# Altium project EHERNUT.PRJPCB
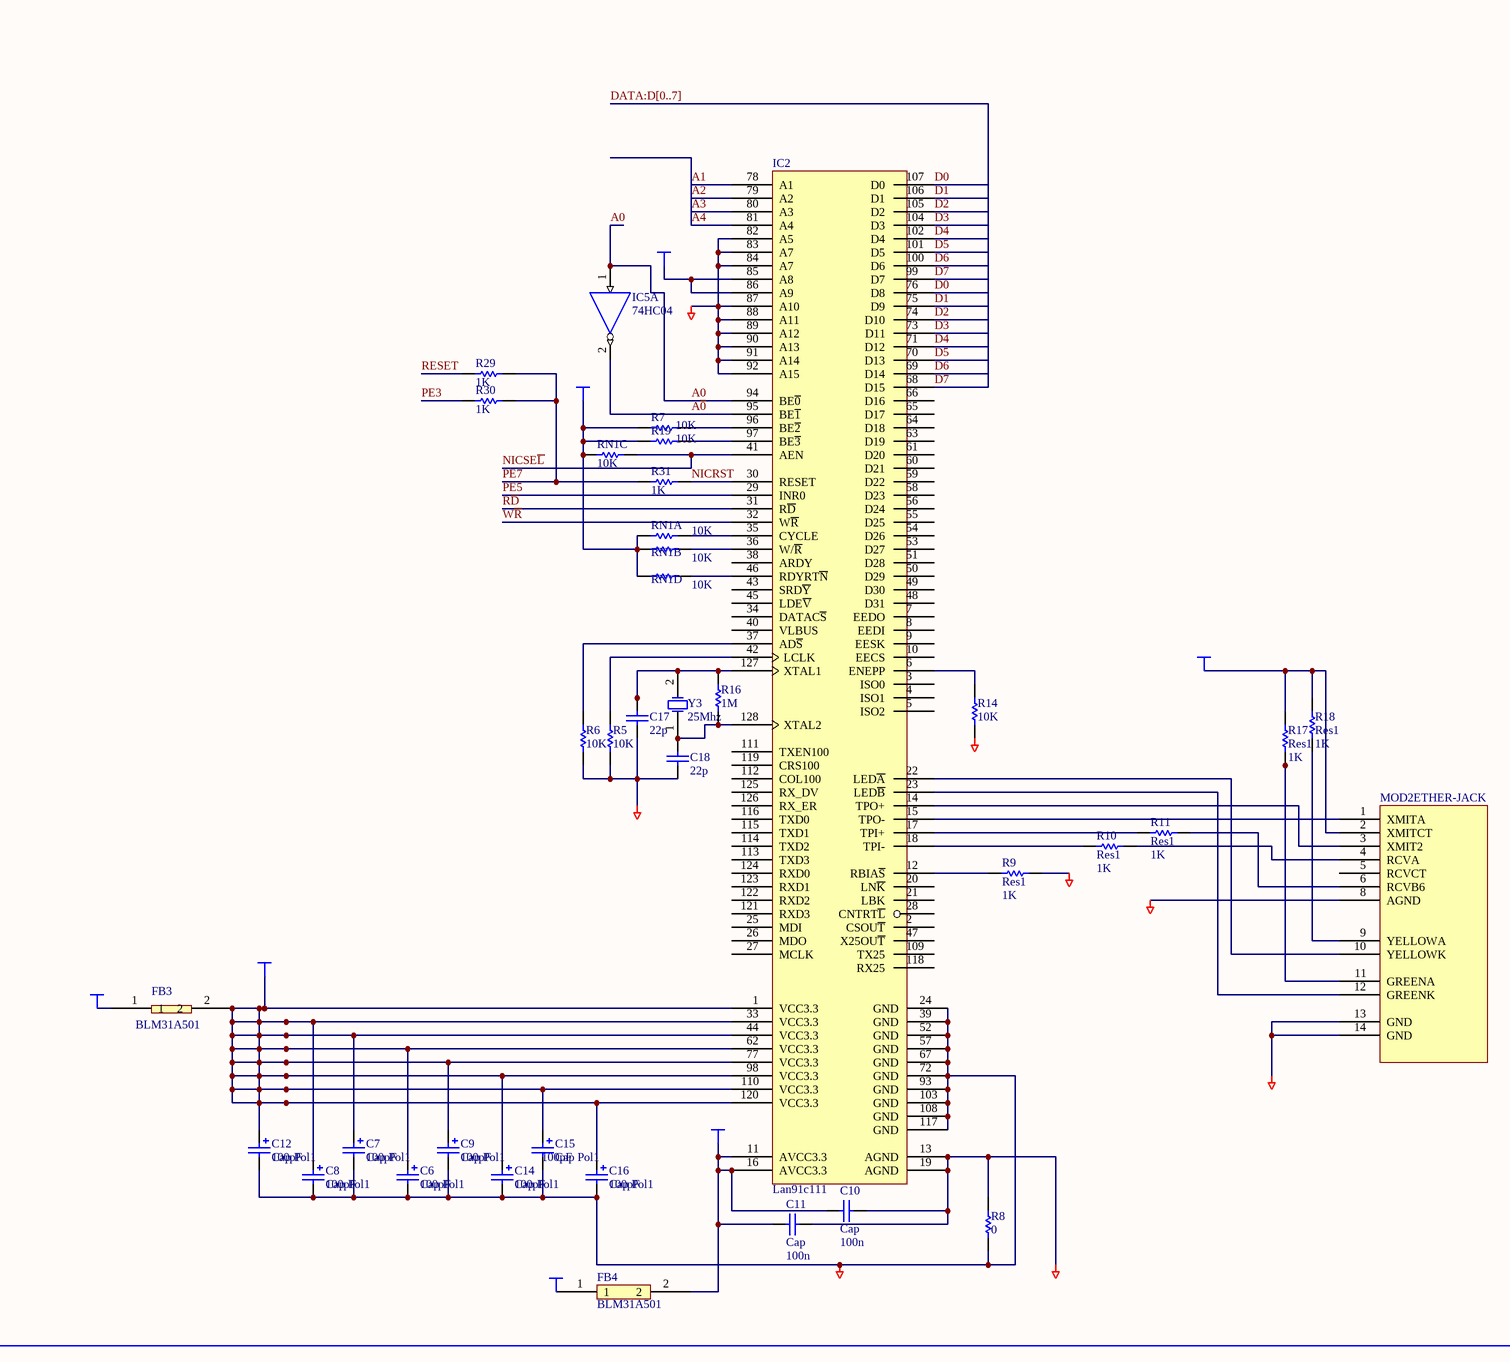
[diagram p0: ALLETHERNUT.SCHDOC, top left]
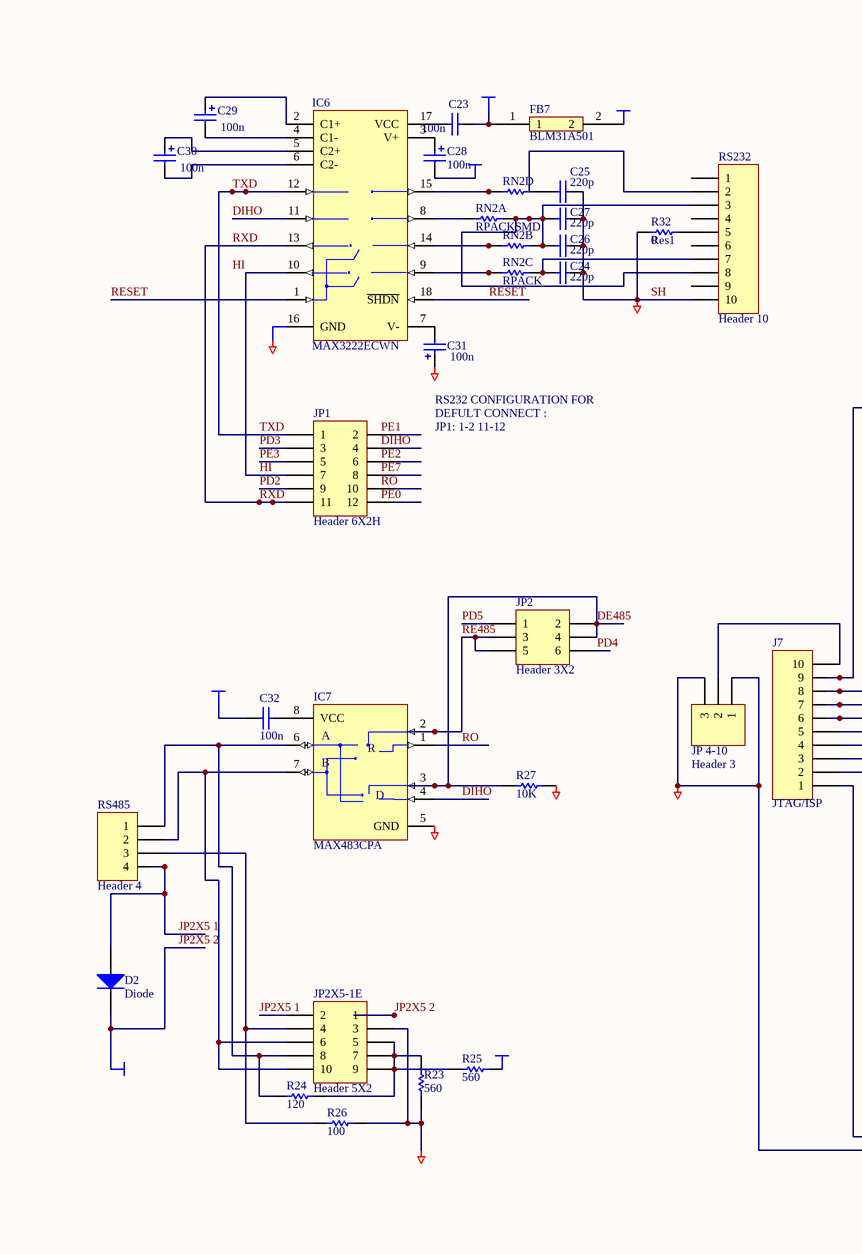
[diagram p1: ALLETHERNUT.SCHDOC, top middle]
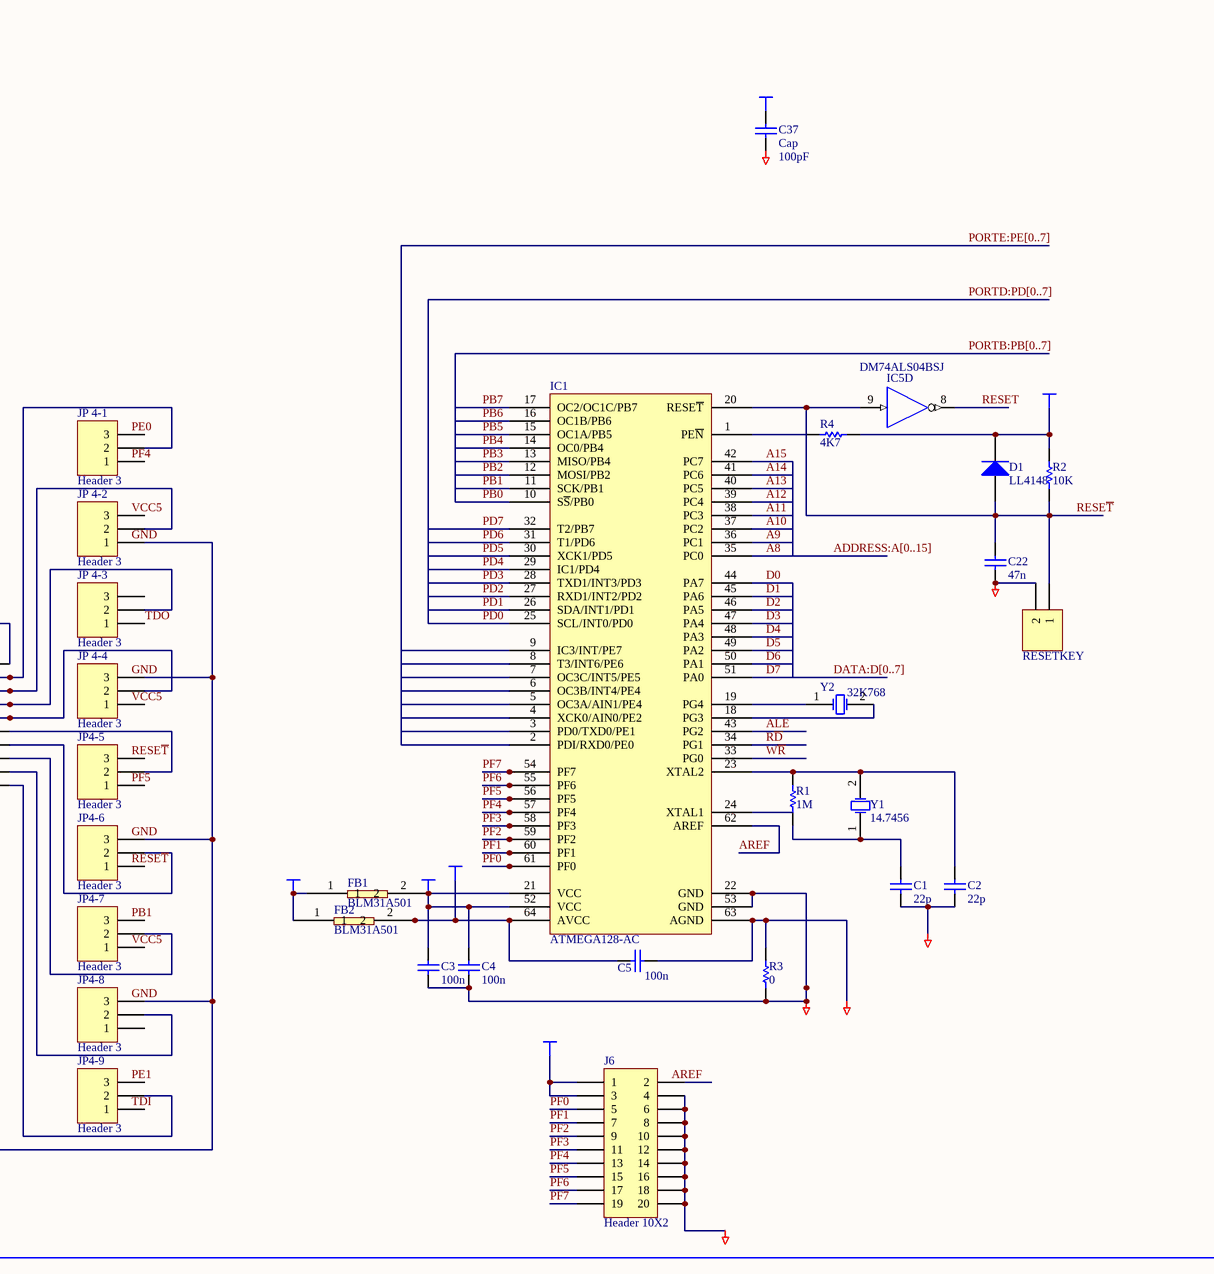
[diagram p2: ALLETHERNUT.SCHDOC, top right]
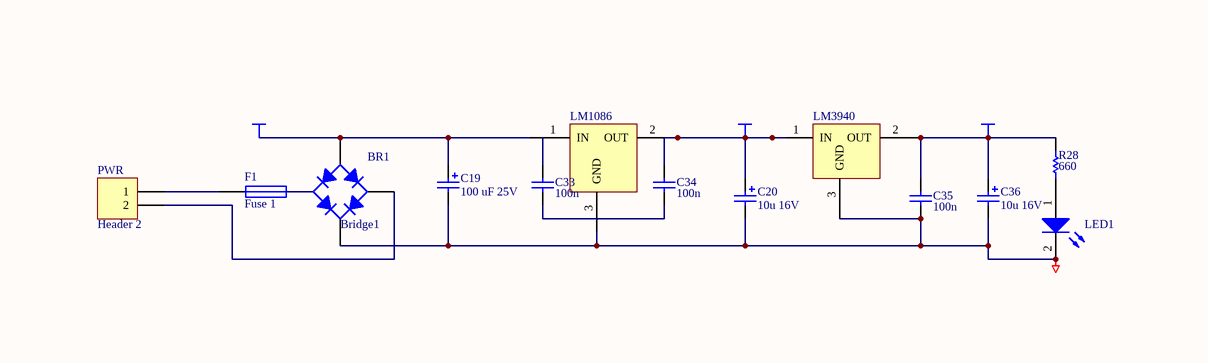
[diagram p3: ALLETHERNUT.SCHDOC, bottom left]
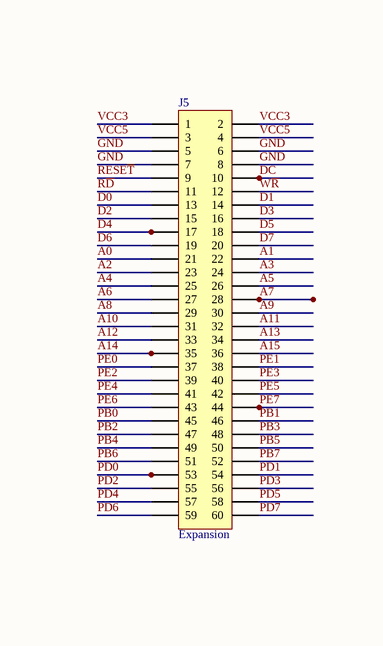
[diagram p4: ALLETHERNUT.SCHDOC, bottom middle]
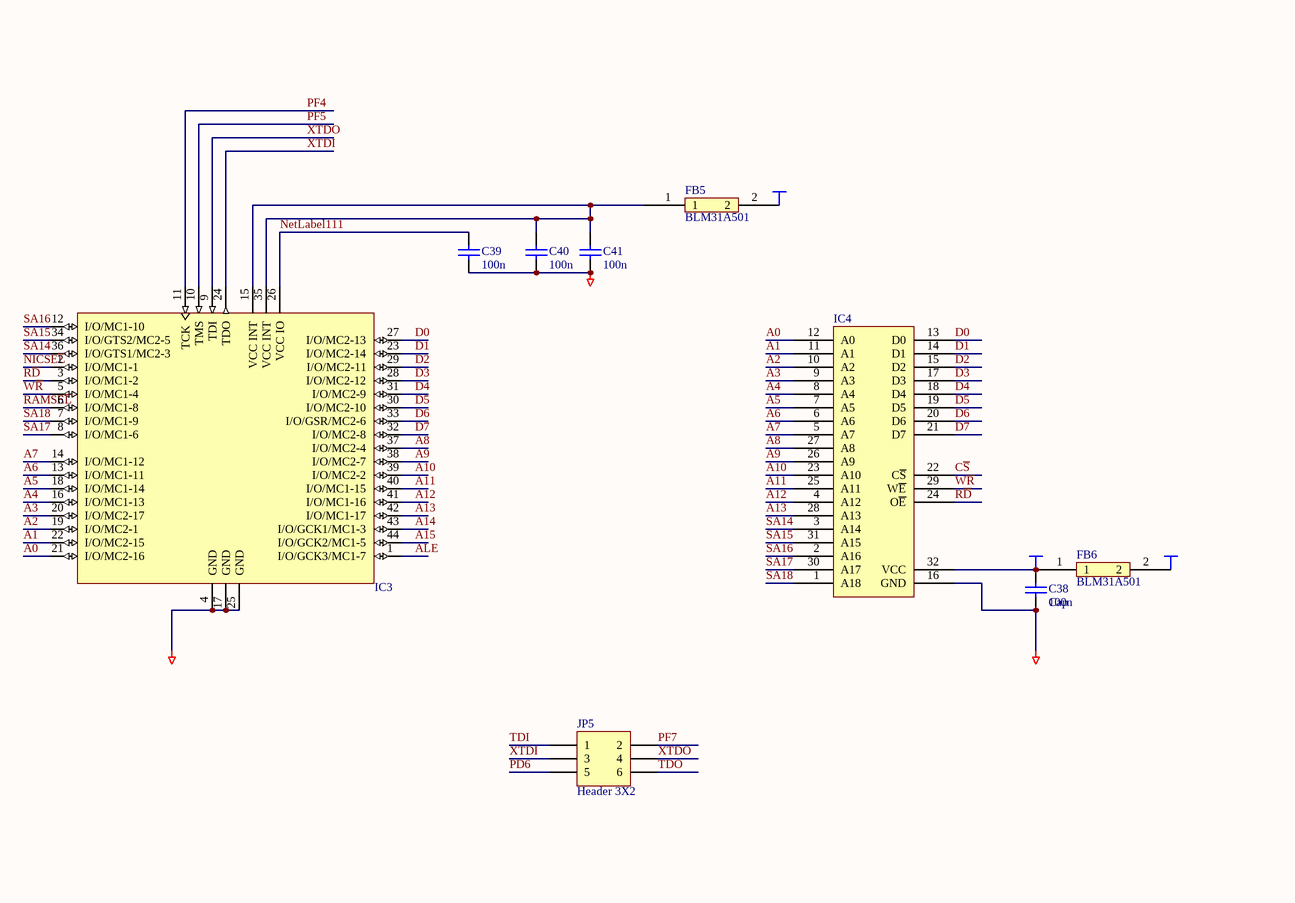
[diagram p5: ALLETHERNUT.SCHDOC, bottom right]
5 sheets, 240 parts. Net scope: global (net labels, ports and power ports of the same name join across sheets).
Sheets:
  ALLETHERNUT.SCHDOC
  ATMEGA128.SCHDOC
  CPLD.SCHDOC
  LAN91C111.SCHDOC
  power.SCHDOC

## Sheet ALLETHERNUT.SCHDOC
size D

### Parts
(Parts that share a designator on the sheet are numbered #1, #2 ... from top to bottom, then left to right.)
?#1  LM3940
BR1#1  Bridge1  [E-BIP-P4/D10]
C1#1  value 22p  [RAD-0.3]
C2#1  value 22p  [RAD-0.3]
C3#1  value 100n  [RAD-0.1]
C4#1  value 100n  [RAD-0.1]
C5#1  value 100n  [RAD-0.1]
C6#1  Cap Pol1  value 100pF  [RAD-0.1]
C7#1  Cap Pol1  value 100pF  [RAD-0.1]
C8#1  Cap Pol1  value 100pF  [RAD-0.1]
C9#1  Cap Pol1  value 100pF  [RAD-0.1]
C10#1  Cap  value 100n  [RAD-0.3]
C11#1  Cap  value 100n  [RAD-0.3]
C12#1  Cap Pol1  value 100pF  [RAD-0.1]
C14#1  Cap Pol1  value 100pF  [RAD-0.1]
C15#1  Cap Pol1  value 100pF  [RAD-0.1]
C16#1  Cap Pol1  value 100pF  [RAD-0.1]
C17#1  value 22p  [RAD-0.1]
C18#1  value 22p  [RAD-0.1]
C19#1  value 100 uF 25V  [RAD-0.1]
C20#1  value 10u 16V  [RAD-0.1]
C22#1  value 47n  [RAD-0.1]
C23#1  value 100n  [RAD-0.1]
C24#1  value 220p  [RAD-0.1]
C25#1  value 220p  [RAD-0.1]
C26#1  value 220p  [RAD-0.1]
C27#1  value 220p  [RAD-0.1]
C28#1  value 100n  [RAD-0.1]
C29#1  value 100n  [RAD-0.1]
C30#1  value 100n  [RAD-0.1]
C31#1  value 100n  [RAD-0.1]
C32#1  value 100n  [RAD-0.1]
C33#1  value 100n  [RAD-0.1]
C34#1  value 100n  [RAD-0.1]
C35#1  value 100n  [RAD-0.1]
C36#1  value 10u 16V  [RAD-0.1]
C37#1  Cap  value 100pF  [RAD-0.1]
C38#1  Cap  value 100n  [RAD-0.1]
C39#1  value 100n  [RAD-0.1]
C40#1  value 100n  [RAD-0.1]
C41#1  value 100n  [RAD-0.1]
D1#1  LL4148  [HDR1X2]
D2#1  Diode  [HDR1X2]
F1#1  Fuse 1  [PIN-W2/E2.8]
FB1#1  BLM31A501
FB2#1  BLM31A501
FB3#1  BLM31A501
FB4#1  BLM31A501
FB5#1  BLM31A501
FB6#1  BLM31A501
FB7#1  BLM31A501
IC1  ATMEGA128-AC  [F-QFP10X10-G64/P.5N]
IC2  Lan91c111  [FR-QFP14X20-G128/X.3N]
IC3#1  (no value)  [QFP10x10-G44/X.5N]
IC4#1  k6t4008  [SO-G32/Y1.45]
IC5#1  74HC04  [DIP-14/D19.7]  (part A of 6)
IC5#2  DM74ALS04BSJ  [SO-G14/Y1.7]  (part D of 6)
IC6#1  MAX3222ECWN  [DIP-18]
IC7#1  MAX483CPA  [DIP-8]
J5#1  Expansion  [HDR2X30]
J6#1  Header 10X2  [HDR2X10]
J7#1  JTAG/ISP  [HDR1X10]
JP1#1  Header 6X2H  [HDR2X6]
JP2#1  Header 3X2  [HDR2X3]
JP2X5-1E#1  Header 5X2  [HDR2X5]
JP4-5#1  Header 3  [HDR1X3]
JP4-6#1  Header 3  [HDR1X3]
JP4-7#1  Header 3  [HDR1X3]
JP4-8#1  Header 3  [HDR1X3]
JP4-9#1  Header 3  [HDR1X3]
JP5#1  Header 3X2  [HDR2X3]
JP_4-1#1  Header 3  [HDR1X3]
JP_4-2#1  Header 3  [HDR1X3]
JP_4-3#1  Header 3  [HDR1X3]
JP_4-4#1  Header 3  [HDR1X3]
JP_4-10#1  Header 3  [HDR1X3]
LED1#1  (no value)  [HDR1X2]
LM1086#1  (no value)  [Model Name]
MOD2ETHER-JACK#1  (no value)
PWR#1  Header 2  [HDR1X2]
R1#1  value 1M  [AXIAL-0.3]
R2#1  value 10K  [AXIAL-0.3]
R3#1  value 0  [AXIAL-0.3]
R4#1  value 4K7  [AXIAL-0.3]
R5#1  value 10K  [AXIAL-0.3]
R6#1  value 10K  [C3216-1206]
R7#1  value 10K  [AXIAL-0.3]
R8#1  value 0  [AXIAL-0.3]
R9#1  Res1  value 1K  [AXIAL-0.3]
R10#1  Res1  value 1K  [AXIAL-0.3]
R11#1  Res1  value 1K  [AXIAL-0.3]
R14#1  value 10K  [AXIAL-0.3]
R16#1  value 1M  [AXIAL-0.3]
R17#1  Res1  value 1K  [AXIAL-0.3]
R18#1  Res1  value 1K  [AXIAL-0.3]
R19#1  value 10K  [AXIAL-0.3]
R23#1  value 560  [AXIAL-0.3]
R24#1  value 120  [AXIAL-0.3]
R25#1  value 560  [AXIAL-0.3]
R26#1  value 100  [AXIAL-0.3]
R27#1  value 10K  [AXIAL-0.3]
R28#1  value 660  [AXIAL-0.3]
R29#1  value 1K  [AXIAL-0.3]
R30#1  value 1K  [AXIAL-0.3]
R31#1  value 1K  [AXIAL-0.3]
R32#1  Res1  value 0  [AXIAL-0.3]
RESETKEY#1  (no value)  [HDR1X2]
RN1A#1  value 10K  [C3225-1210]
RN1B#1  value 10K  [AXIAL-0.3]
RN1C#1  value 10K  [AXIAL-0.3]
RN1D#1  value 10K  [AXIAL-0.3]
RN2A#1  RPACKSMD  [AXIAL-0.3]
RN2B#1  (no value)  [AXIAL-0.3]
RN2C#1  RPACK  [AXIAL-0.3]
RN2D#1  (no value)  [AXIAL-0.3]
RS232#1  Header 10  [DSUB1.385-2H9]
RS485#1  Header 4  [DSUB1.385-2H9]
Y1#1  14.7456  [BCY-W2/D3.1]
Y2#1  32K768  [BCY-W2/D3.1]
Y3#1  25Mhz  [RAD-0.3]

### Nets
AGND3: C10#1.2 C11#1.2 IC2.13(AGND) IC2.19(AGND) MOD2ETHER-JACK#1.8(AGND) R8#1.2 R9#1.2
AGND5: C5#1.2 IC1.63(AGND) J6#1.4 J6#1.6 J6#1.8 J6#1.10 J6#1.12 J6#1.14 J6#1.16 J6#1.18 J6#1.20 R3#1.2
AVCC3: C10#1.1 C11#1.1 FB4#1.2 IC2.11(AVCC3.3) IC2.16(AVCC3.3) MOD2ETHER-JACK#1.2(XMITCT) R17#1.2 R18#1.2
AVCC5: C5#1.1 FB2#1.2 IC1.64(AVCC) J6#1.1 J6#1.3
DC: BR1#1.1(A) C19#1.1 D2#1.2(K) J5#1.10 JP2X5-1E#1.1 LM1086#1.1(IN)  [also labelled JP2X5 2]
GND: ?#1.3(GND) BR1#1.3(K) C1#1.1 C2#1.1 C3#1.1 C4#1.1 C6#1.2 C7#1.2 C8#1.2 C9#1.2 C12#1.2 C14#1.2 C15#1.2 C16#1.2 C17#1.1 C18#1.1 C19#1.2 C20#1.2 C22#1.1 C24#1.2 C25#1.2 C26#1.2 C27#1.2 C31#1.1 C35#1.1 C36#1.2 C37#1.1 C38#1.1 C39#1.1 C40#1.1 C41#1.1 IC1.22(GND) IC1.53(GND) IC2.24(GND) IC2.39(GND) IC2.52(GND) IC2.57(GND) IC2.67(GND) IC2.72(GND) IC2.82(A5) IC2.83(A7) IC2.84(A7) IC2.87(A10) IC2.88(A11) IC2.89(A12) IC2.90(A13) IC2.91(A14) IC2.92(A15) IC2.93(GND) IC2.103(GND) IC2.108(GND) IC2.117(GND) IC3#1.4(GND) IC3#1.17(GND) IC3#1.25(GND) IC4#1.16(GND) IC7#1.5(GND) J5#1.5 J5#1.6 J5#1.7 J5#1.8 JP2X5-1E#1.3 JP4-6#1.3 JP4-8#1.3 JP_4-2#1.1 JP_4-4#1.3 JP_4-10#1.1 JP_4-10#1.3 LED1#1.2(K) LM1086#1.3(GND) MOD2ETHER-JACK#1.13(GND) MOD2ETHER-JACK#1.14(GND) R3#1.1 R5#1.1 R6#1.1 R8#1.1 R14#1.1 R23#1.1 R26#1.2 R27#1.2 R32#1.1 RESETKEY#1.2 RS232#1.10  [also labelled SH]
VCC3: ?#1.2(OUT) C35#1.2 C36#1.1 FB3#1.1 FB4#1.1 FB5#1.2 J5#1.1 J5#1.2 R28#1.2
VCC3N: C6#1.1 C7#1.1 C8#1.1 C9#1.1 C12#1.1 C14#1.1 C15#1.1 C16#1.1 FB3#1.2 IC2.1(VCC3.3) IC2.33(VCC3.3) IC2.44(VCC3.3) IC2.62(VCC3.3) IC2.77(VCC3.3) IC2.85(A8) IC2.86(A9) IC2.98(VCC3.3) IC2.110(VCC3.3) IC2.120(VCC3.3) R7#1.1 R19#1.1 RN1A#1.1 RN1B#1.1 RN1C#1.1 RN1D#1.1
VCC5: ?#1.1(IN) C20#1.1 C32#1.1 C34#1.2 C37#1.2 FB1#1.1 FB2#1.1 FB6#1.2 FB7#1.2 J5#1.3 J5#1.4 LM1086#1.2(OUT) R25#1.2
VCC5P: C3#1.2 C4#1.2 D1#1.2(K) FB1#1.2 IC1.21(VCC) IC1.52(VCC) R2#1.2 R4#1.2
VCC5R: C38#1.2 FB6#1.1 IC4#1.32(VCC)
VCC5S: C23#1.2 C28#1.2 FB7#1.1
A0: IC2.94(BE~{0}) IC3#1.21(I/O/MC2-16) IC4#1.12(A0) IC5#1.1(A) J5#1.21
A~{0}: IC2.95(BE~{1}) IC5#1.2(Y)
A1: IC2.78(A1) IC3#1.22(I/O/MC2-15) IC4#1.11(A1) J5#1.22
A2: IC2.79(A2) IC3#1.19(I/O/MC2-1) IC4#1.10(A2) J5#1.23
A3: IC2.80(A3) IC3#1.20(I/O/MC2-17) IC4#1.9(A3) J5#1.24
A4: IC2.81(A4) IC3#1.16(I/O/MC1-13) IC4#1.8(A4) J5#1.25
A5: IC3#1.18(I/O/MC1-14) IC4#1.7(A5) J5#1.26
A6: IC3#1.13(I/O/MC1-11) IC4#1.6(A6) J5#1.27
A7: IC3#1.14(I/O/MC1-12) IC4#1.5(A7) J5#1.28
A8: IC1.35(PC0) IC3#1.37(I/O/MC2-4) IC4#1.27(A8) J5#1.29
A9: IC1.36(PC1) IC3#1.38(I/O/MC2-7) IC4#1.26(A9) J5#1.30
A10: IC1.37(PC2) IC3#1.39(I/O/MC2-2) IC4#1.23(A10) J5#1.31
A11: IC1.38(PC3) IC3#1.40(I/O/MC1-15) IC4#1.25(A11) J5#1.32
A12: IC1.39(PC4) IC3#1.41(I/O/MC1-16) IC4#1.4(A12) J5#1.33
A13: IC1.40(PC5) IC3#1.42(I/O/MC1-17) IC4#1.28(A13) J5#1.34
A14: IC1.41(PC6) IC3#1.43(I/O/GCK1/MC1-3) J5#1.35
A15: IC1.42(PC7) IC3#1.44(I/O/GCK2/MC1-5) J5#1.36
ALE: IC1.43(PG2) IC3#1.1(I/O/GCK3/MC1-7)
AREF: IC1.62(AREF)
C~{S}: IC4#1.22(C~{S})
D0: IC1.44(PA7) IC2.76(D8) IC2.107(D0) IC3#1.27(I/O/MC2-13) IC4#1.13(D0) J5#1.13
D1: IC1.45(PA6) IC2.75(D9) IC2.106(D1) IC3#1.23(I/O/MC2-14) IC4#1.14(D1) J5#1.14
D2: IC1.46(PA5) IC2.74(D10) IC2.105(D2) IC3#1.29(I/O/MC2-11) IC4#1.15(D2) J5#1.15
D3: IC1.47(PA4) IC2.73(D11) IC2.104(D3) IC3#1.28(I/O/MC2-12) IC4#1.17(D3) J5#1.16
D4: IC1.48(PA3) IC2.71(D12) IC2.102(D4) IC3#1.31(I/O/MC2-9) IC4#1.18(D4) J5#1.17
D5: IC1.49(PA2) IC2.70(D13) IC2.101(D5) IC3#1.30(I/O/MC2-10) IC4#1.19(D5) J5#1.18
D6: IC1.50(PA1) IC2.69(D14) IC2.100(D6) IC3#1.33(I/O/GSR/MC2-6) IC4#1.20(D6) J5#1.19
D7: IC1.51(PA0) IC2.68(D15) IC2.99(D7) IC3#1.32(I/O/MC2-8) IC4#1.21(D7) J5#1.20
DE485: IC7#1.3(DE) JP2#1.2 JP2#1.4 R27#1.1
DIHO: IC6#1.11(T2IN) IC7#1.4(DI)
HI: IC6#1.10(R2OUT) JP1#1.7
JP2X5 1: D2#1.1(A) JP2X5-1E#1.2 RS485#1.4
NetLabel111: C39#1.2 IC3#1.26(VCC_IO)
NICRST: IC2.30(RESET) R31#1.2
NICSE~{L}: IC2.41(AEN) IC3#1.2(I/O/MC1-1) RN1C#1.2
PB0: IC1.10(S~{S}/PB0) J5#1.45
PB1: IC1.11(SCK/PB1) J5#1.46
PB2: IC1.12(MOSI/PB2) J5#1.47
PB3: IC1.13(MISO/PB4) J5#1.48
PB4: IC1.14(OC0/PB4) J5#1.49
PB5: IC1.15(OC1A/PB5) J5#1.50
PB6: IC1.16(OC1B/PB6) J5#1.51
PB7: IC1.17(OC2/OC1C/PB7) J5#1.52
PD0: IC1.25(SCL/INT0/PD0) J5#1.53
PD1: IC1.26(SDA/INT1/PD1) J5#1.54
PD2: IC1.27(RXD1/INT2/PD2) J5#1.55 JP1#1.9
PD3: IC1.28(TXD1/INT3/PD3) J5#1.56 JP1#1.3
PD4: IC1.29(IC1/PD4) J5#1.57 JP2#1.6
PD5: IC1.30(XCK1/PD5) J5#1.58 JP2#1.1
PD6: IC1.31(T1/PD6) J5#1.59 JP5#1.5
PD7: IC1.32(T2/PB7) J5#1.60
PE0: J5#1.37
PE1: J5#1.38
PE2: J5#1.39
PE3: J5#1.40 JP1#1.5 R30#1.1
PE4: J5#1.41
PE5: IC2.29(INR0) J5#1.42
PE6: J5#1.43
PE7: J5#1.44 R29#1.2 R30#1.2 R31#1.1
PF0: IC1.61(PF0) J6#1.5
PF1: IC1.60(PF1) J6#1.7
PF2: IC1.59(PF2) J6#1.9
PF3: IC1.58(PF3) J6#1.11
PF4: IC1.57(PF4) IC3#1.11(TCK) J6#1.13
PF5: IC1.56(PF5) IC3#1.10(TMS) J6#1.15
PF6: IC1.55(PF6) J6#1.17
PF7: IC1.54(PF7) J6#1.19 JP5#1.2
RAMSE~{L}: IC3#1.6(I/O/MC1-8)
R~{D}: IC1.34(PG1) IC2.31(R~{D}) IC3#1.3(I/O/MC1-2) IC4#1.24(O~{E}) J5#1.11
RE485: IC7#1.2(~{RE}) JP2#1.3 JP2#1.5
RESET: IC5#2.8(Y) IC6#1.1(~{EN}) R29#1.1
RESE~{T}: C22#1.2 D1#1.1(A) IC1.1(PE~{N}) IC1.20(RESE~{T}) IC5#2.9(A) IC6#1.18(~{SHDN}) J5#1.9 R2#1.1 R4#1.1 RESETKEY#1.1
RO: IC7#1.1(RO)
RXD: IC6#1.13(R1OUT) JP1#1.11
SA14: IC3#1.36(I/O/GTS1/MC2-3) IC4#1.3(A14)
SA15: IC3#1.34(I/O/GTS2/MC2-5) IC4#1.31(A15)
SA16: IC3#1.12(I/O/MC1-10) IC4#1.2(A16)
SA17: IC3#1.8(I/O/MC1-6) IC4#1.30(A17)
SA18: IC3#1.7(I/O/MC1-9) IC4#1.1(A18)
TDI: JP5#1.1
TDO: JP5#1.6 JP_4-3#1.1
TXD: IC6#1.12(T1IN) JP1#1.1
W~{R}: IC1.33(PG0) IC2.32(W~{R}) IC3#1.5(I/O/MC1-4) IC4#1.29(W~{E}) J5#1.12
XTDI: IC3#1.24(TDO) JP5#1.3
XTDO: IC3#1.9(TDI) JP5#1.4
NetBR1#1_2: BR1#1.2(C) PWR#1.2
NetBR1#1_4: BR1#1.4(C) F1#1.2
NetC1#1_2: C1#1.2 R1#1.1 Y1#1.1(OSC1)
NetC2#1_2: C2#1.2 IC1.23(XTAL2) R1#1.2 Y1#1.2(OSC2)
NetC17#1_2: C17#1.2 IC2.127(XTAL1) R16#1.2 Y3#1.2(OSC2)
NetC18#1_2: C18#1.2 IC2.128(XTAL2) R16#1.1 Y3#1.1(OSC1)
NetC23#1_1: C23#1.1 IC6#1.17(VCC)
NetC24#1_1: C24#1.1 RN2C#1.2 RS232#1.7
NetC25#1_1: C25#1.1 RN2D#1.2
NetC26#1_1: C26#1.1 C27#1.1 RN2A#1.2 RN2B#1.2 RS232#1.3 RS232#1.8
NetC28#1_1: C28#1.1 IC6#1.3(V+)
NetC29#1_1: C29#1.1 IC6#1.2(C1+)
NetC29#1_2: C29#1.2 IC6#1.4(C1-)
NetC30#1_1: C30#1.1 IC6#1.5(C2+)
NetC30#1_2: C30#1.2 IC6#1.6(C2-)
NetC31#1_2: C31#1.2 IC6#1.7(V-)
NetC32#1_2: C32#1.2 IC7#1.8(VCC)
NetC33#1_1: C33#1.1 C34#1.1
NetC40#1_2: C40#1.2 C41#1.2 FB5#1.1 IC3#1.15(VCC_INT) IC3#1.35(VCC_INT)
NetF1#1_1: F1#1.1 PWR#1.1
NetIC1_18: IC1.18(PG3) Y2#1.2(OSC2)
NetIC1_19: IC1.19(PG4) Y2#1.1(OSC1)
NetIC2_6: IC2.6(ENEPP) R14#1.2
NetIC2_12: IC2.12(RBIA~{S}) R9#1.1
NetIC2_14: IC2.14(TPO+) MOD2ETHER-JACK#1.3(XMIT2)
NetIC2_15: IC2.15(TPO-) MOD2ETHER-JACK#1.1(XMITA)
NetIC2_17: IC2.17(TPI+) R11#1.1
NetIC2_18: IC2.18(TPI-) R10#1.1
NetIC2_22: IC2.22(LED~{A}) MOD2ETHER-JACK#1.10(YELLOWK)
NetIC2_23: IC2.23(LED~{B}) MOD2ETHER-JACK#1.12(GREENK)
NetIC2_35: IC2.35(CYCLE) RN1A#1.2
NetIC2_36: IC2.36(W/~{R}) RN1B#1.2
NetIC2_37: IC2.37(AD~{S}) R6#1.2
NetIC2_42: IC2.42(LCLK) R5#1.2
NetIC2_46: IC2.46(RDYRT~{N}) RN1D#1.2
NetIC2_96: IC2.96(BE~{2}) R7#1.2
NetIC2_97: IC2.97(BE~{3}) R19#1.2
NetIC6#1_8: IC6#1.8(T2OUT) RN2A#1.1
NetIC6#1_9: IC6#1.9(R2IN) RN2C#1.1
NetIC6#1_14: IC6#1.14(R1IN) RN2B#1.1
NetIC6#1_15: IC6#1.15(T1OUT) RN2D#1.1
NetIC7#1_6: IC7#1.6(A) JP2X5-1E#1.8 R24#1.1 RS485#1.1
NetIC7#1_7: IC7#1.7(B) JP2X5-1E#1.6 JP2X5-1E#1.10 RS485#1.2
NetJ7#1_1: J7#1.1 JP4-9#1.2
NetJ7#1_2: J7#1.2 JP4-8#1.2
NetJ7#1_3: J7#1.3 JP4-7#1.2
NetJ7#1_4: J7#1.4 JP4-6#1.2
NetJ7#1_5: J7#1.5 JP4-5#1.2
NetJ7#1_6: J7#1.6 JP_4-4#1.2
NetJ7#1_7: J7#1.7 JP_4-3#1.2
NetJ7#1_8: J7#1.8 JP_4-2#1.2
NetJ7#1_9: J7#1.9 JP_4-1#1.2
NetJ7#1_10: J7#1.10 JP_4-10#1.2
NetJP2X5-1E#1_4: JP2X5-1E#1.4 R26#1.1 RS485#1.3
NetJP2X5-1E#1_5: JP2X5-1E#1.5 JP2X5-1E#1.7 JP2X5-1E#1.9 R23#1.2 R24#1.2 R25#1.1
NetLED1#1_1: LED1#1.1(A) R28#1.1
NetMOD2ETHER-JACK#1_4: MOD2ETHER-JACK#1.4(RCVA) R10#1.2
NetMOD2ETHER-JACK#1_6: MOD2ETHER-JACK#1.6(RCVB6) R11#1.2
NetMOD2ETHER-JACK#1_9: MOD2ETHER-JACK#1.9(YELLOWA) R18#1.1
NetMOD2ETHER-JACK#1_11: MOD2ETHER-JACK#1.11(GREENA) R17#1.1
NetR32#1_2: R32#1.2 RS232#1.5

Not connected (* = marked no-connect by the designer): C33#1 2; IC1 2(PDI/RXD0/PE0) 3(PD0/TXD0/PE1) 4(XCK0/AIN0/PE2) 5(OC3A/AIN1/PE4) 6(OC3B/INT4/PE4) 7(OC3C/INT5/PE5) 8(T3/INT6/PE6) 9(IC3/INT/PE7) 24(XTAL1); IC2 2(CSOU~{T}) 3(ISO0) 4(ISO1) 5(ISO2) 7(EEDO) 8(EEDI) 9(EESK) 10(EECS) 20(LN~{K}) 21(LBK) 25(MDI) 26(MDO) 27(MCLK) 28(CNTRT~{L}) 34(DATAC~{S}) 38(ARDY) 40(VLBUS) 43(SRD~{Y}) 45(LDE~{V}) 47(X25OU~{T}) 48(D31) 49(D30) 50(D29) 51(D28) 53(D27) 54(D26) 55(D25) 56(D24) 58(D23) 59(D22) 60(D21) 61(D20) 63(D19) 64(D18) 65(D17) 66(D16) 109(TX25) 111(TXEN100) 112(COL100) 113(TXD3) 114(TXD2) 115(TXD1) 116(TXD0) 118(RX25) 119(CRS100) 121(RXD3) 122(RXD2) 123(RXD1) 124(RXD0) 125(RX_DV) 126(RX_ER); IC5#1 7(GND) 14(VCC); IC5#2 7(GND) 14(VCC5); IC6#1 16(GND); J6#1 2; JP1#1 2 4 6 8 10 12; JP4-5#1 1 3; JP4-6#1 1; JP4-7#1 1 3; JP4-8#1 1; JP4-9#1 1 3; JP_4-1#1 1 3; JP_4-2#1 3; JP_4-3#1 3; JP_4-4#1 1; MOD2ETHER-JACK#1 5(RCVCT); RS232#1 1 2 4 6 9

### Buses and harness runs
bus ADDRESS:A[0..15]
bus DATA:D[0..7]
bus PORTB:PB[0..7]
bus PORTD:PD[0..7]
bus PORTE:PE[0..7]

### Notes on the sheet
- (near C31#1) RS232 CONFIGURATION FOR
- DEFULT CONNECT :
- JP1: 1-2 11-12
- Labels drawn without touching a wire or pin: AREF, DIHO, GND, HI, PB1, PE0, PE1, PE2, PE7, PF4, PF5, RESE~{T}, RO, TDI, VCC5

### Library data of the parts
BR1#1 = Bridge1: Full Wave Diode Bridge; Manufacturer: Generic Components; Class: Discrete; SubClass: Rectifier - Bridge
C1#1 C2#1 C3#1 C4#1 C5#1 C10#1 C11#1 C17#1 C18#1 C22#1 C23#1 C24#1 C25#1 C26#1 C27#1 C32#1 C37#1 C38#1 C39#1 C40#1 C41#1 = Cap: Capacitor; Manufacturer: Generic Components; Class: Passive
C6#1 C7#1 C8#1 C9#1 C12#1 C14#1 C15#1 C16#1 = Cap Pol1: Polarized Capacitor (Radial); Manufacturer: Generic Components; Class: Passive
C19#1 C20#1 C28#1 C29#1 C30#1 C36#1 = Cap Pol2: Polarized Capacitor (Axial); Manufacturer: Generic Components; Class: Passive
C31#1 = (no symbol name): Polarized Capacitor (Axial); Manufacturer: Generic Components; Class: Passive
C33#1 C34#1 C35#1 = Cap Semi: Capacitor (Semiconductor SIM Model); Manufacturer: Generic Components; Class: Passive
D1#1 = Diode: Default Diode; Manufacturer: Generic Components; Class: Discrete
D2#1 = Diode: Default Diode; Manufacturer: Generic Components; Class: Discrete; SubClass: Diode - Switching
F1#1 = Fuse 1: Fuse; Manufacturer: Generic Components; Class: Passive
IC1 = ATMEGA128
IC2 = SMSC: pin to pad: 2>132 3>27 4>21 5>44 6>17 7>51 8>50 9>49 10>48 11>76 12>15 13>130 14>26 15>23 16>110 17>25 18>14 19>131 20>93 21>100 23>39 24>120 25>12 26>13 27>99 28>16 39>11 44>5 48>10 49>53 50>54 51>55 53>56 54>9 55>58 56>59 58>60 59>61 60>62 61>63 63>64 64>65 65>66 66>8 76>2 93>3 99>101 100>102 101>20 102>104 104>105 105>106 106>107 107>24 112>78 113>7 114>6 116>4 117>129 118>98 119>77
IC3#1 = XC9536-10VQ44C: Programmable CPLD; Manufacturer: Xilinx; Class: PLD; SubClass: XC9500
IC5#1 = (no symbol name): Hex Inverter; Manufacturer: Fairchild Semiconductor; Class: Logic; SubClass: Gate
IC5#2 = DM74ALS04BSJ: Hex Inverter; Manufacturer: Fairchild Semiconductor; Class: Logic; SubClass: Gate
IC6#1 = MAX3222ECWN: ±15kV ESD-Protected, 3.0V to 5.5V, Low-Power, up to 250kbps, True RS-232 Transceiver; Manufacturer: Maxim; Class: Communication
IC7#1 = MAX483CPA: Low-Power, Slew-Rate-Limited RS-485/RS-422 Transceiver; Manufacturer: Maxim; Class: Communication
J5#1 = Header 30X2: Header, 30-Pin, Dual row; Manufacturer: Generic Components; Class: Connector
J6#1 = Header 10X2: Header, 10-Pin, Dual row; Manufacturer: Generic Components; Class: Connector
J7#1 RS232#1 = Header 10: Header, 10-Pin; Manufacturer: Generic Components; Class: Connector
JP1#1 = Header 6X2H: Header, 6-Pin, Dual row,  Right Angle; Manufacturer: Generic Components; Class: Connector
JP2#1 JP5#1 = Header 3X2: Header, 3-Pin, Dual row; Manufacturer: Generic Components; Class: Connector
JP2X5-1E#1 = Header 5X2: Header, 5-Pin, Dual row; Manufacturer: Generic Components; Class: Connector
JP4-5#1 JP4-6#1 JP4-7#1 JP4-8#1 JP4-9#1 JP_4-1#1 JP_4-2#1 JP_4-3#1 JP_4-4#1 JP_4-10#1 = Header 3: Header, 3-Pin; Manufacturer: Generic Components; Class: Connector
LED1#1 = LED1: Typical RED GaAs LED; Manufacturer: Generic Components; Class: Optoelectronic
LM1086#1 = LM1086
MOD2ETHER-JACK#1 = ETHER
PWR#1 = Header 2: Header, 2-Pin; Manufacturer: Generic Components; Class: Connector
R1#1 R2#1 R3#1 R4#1 R5#1 R6#1 R8#1 R9#1 R10#1 R11#1 R14#1 R16#1 R17#1 R18#1 R23#1 R24#1 R25#1 R26#1 R27#1 R28#1 R29#1 R30#1 R31#1 R32#1 RN1A#1 RN1B#1 RN1C#1 RN1D#1 = Res1: Resistor; Manufacturer: Generic Components; Class: Passive
R7#1 R19#1 = (no symbol name): Resistor; Manufacturer: Generic Components; Class: Passive
RESETKEY#1 = MHDR1X2: Header, 2-Pin; Manufacturer: Generic Components; Class: Connector
RN2A#1 RN2B#1 RN2D#1 = (no symbol name): Resistor; Manufacturer: Generic Components; Class: Passive; Value: 1K
RN2C#1 = Res1: Resistor; Manufacturer: Generic Components; Class: Passive; Value: 1K
RS485#1 = Header 4: Header, 4-Pin; Manufacturer: Generic Components; Class: Connector
Y1#1 Y2#1 Y3#1 = XTAL: Crystal Oscillator; Manufacturer: Generic Components

## Sheet ATMEGA128.SCHDOC
size B
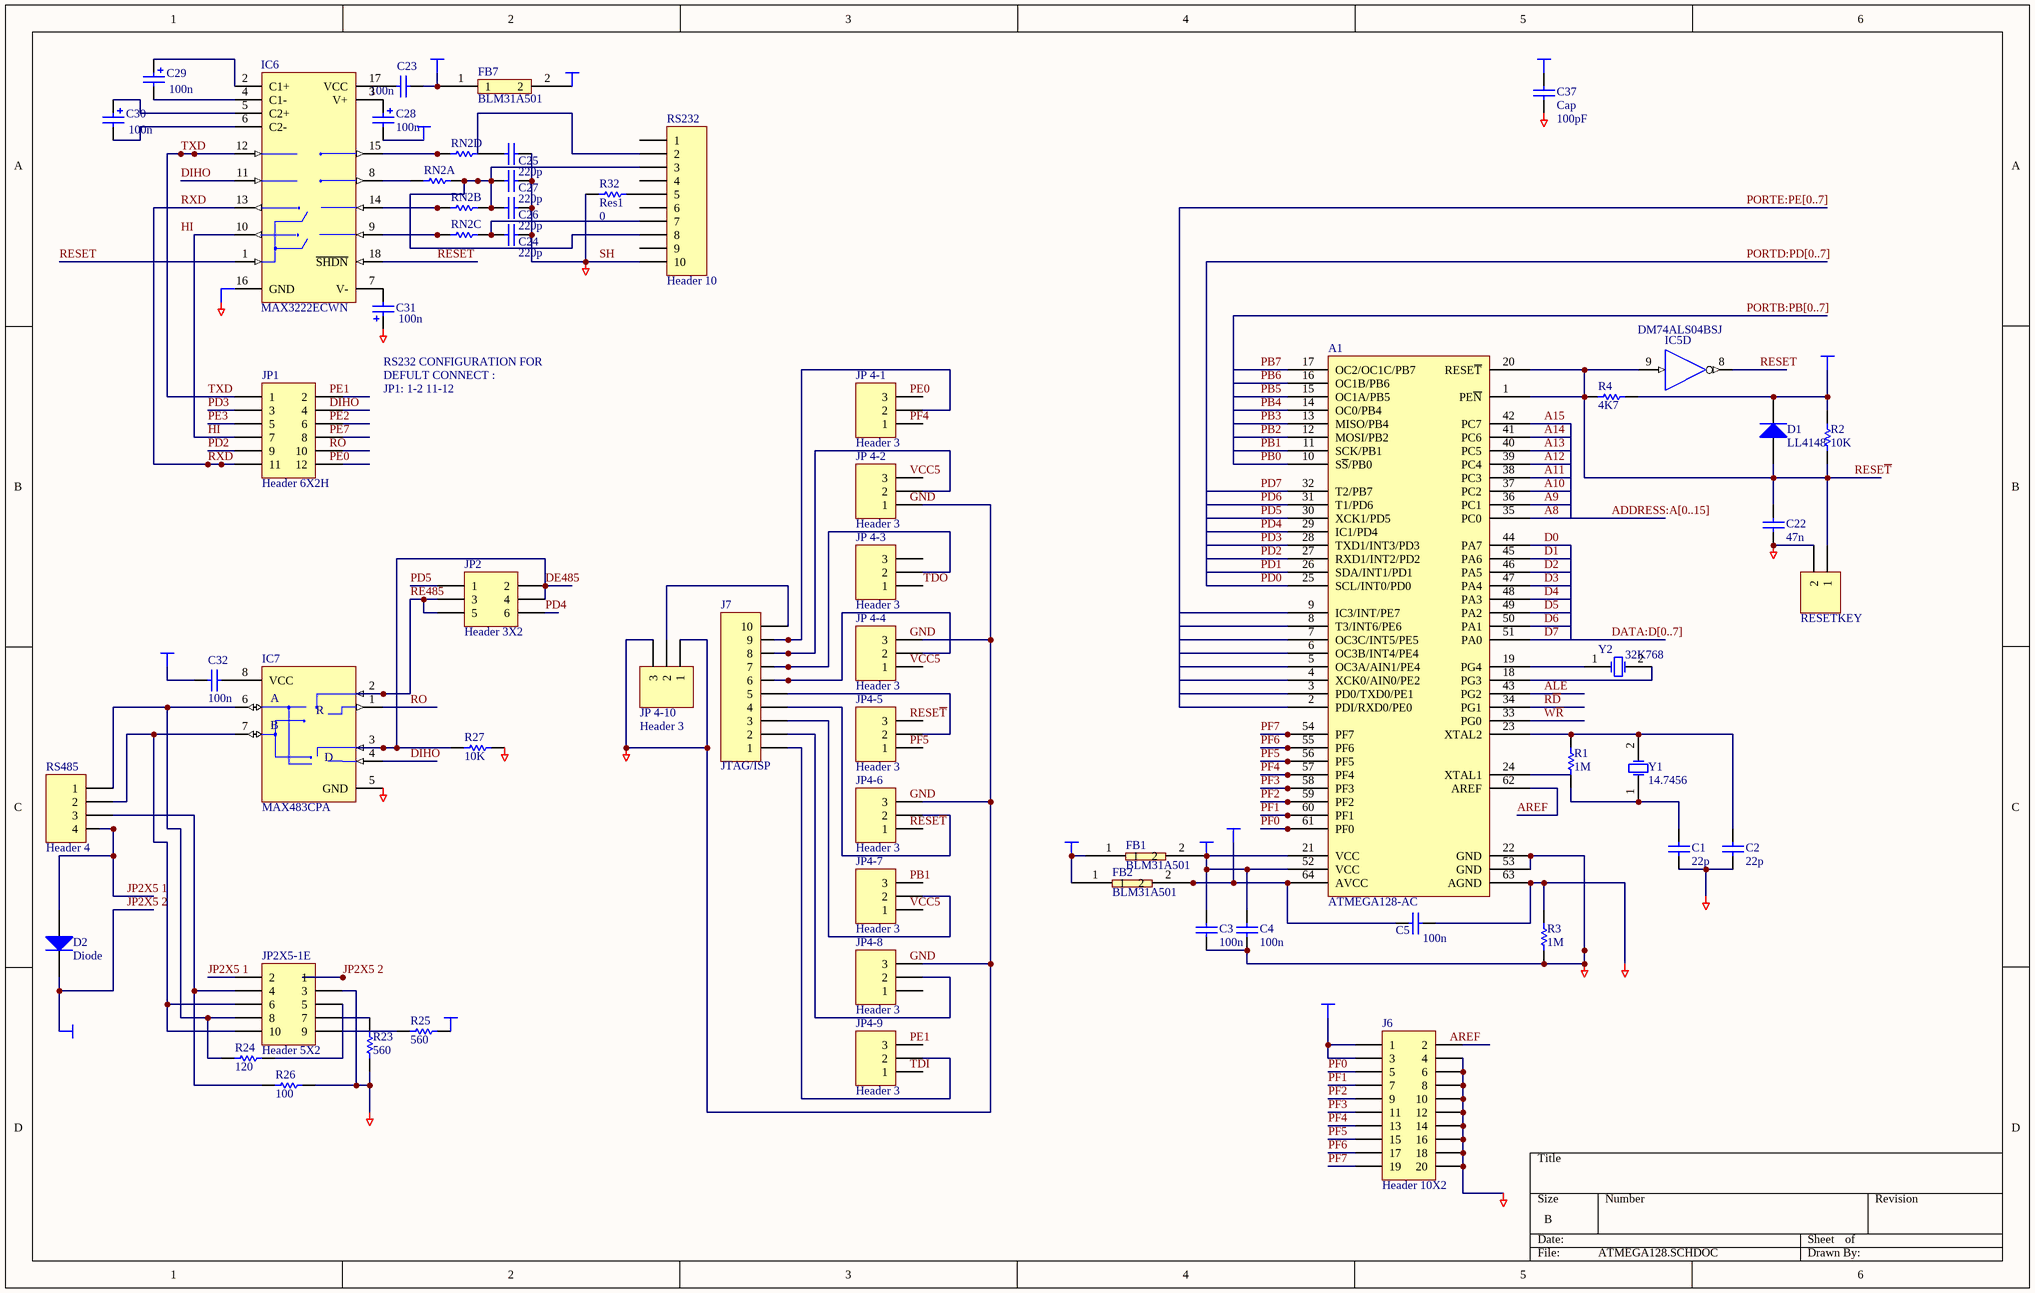
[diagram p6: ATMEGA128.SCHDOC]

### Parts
(Parts that share a designator on the sheet are numbered #1, #2 ... from top to bottom, then left to right.)
A1  ATMEGA128-AC  [Model Name]
C1#2  value 22p  [RAD-0.3]
C2#2  value 22p  [RAD-0.3]
C3#2  value 100n  [RAD-0.1]
C4#2  value 100n  [RAD-0.1]
C5#2  value 100n  [RAD-0.1]
C22#2  value 47n  [RAD-0.1]
C23#2  value 100n  [RAD-0.1]
C24#2  value 220p  [RAD-0.1]
C25#2  value 220p  [RAD-0.1]
C26#2  value 220p  [RAD-0.1]
C27#2  value 220p  [RAD-0.1]
C28#2  value 100n  [RAD-0.1]
C29#2  value 100n  [RAD-0.1]
C30#2  value 100n  [RAD-0.1]
C31#2  value 100n  [RAD-0.1]
C32#2  value 100n  [RAD-0.1]
C37#2  Cap  value 100pF  [RAD-0.1]
D1#2  LL4148  [HDR1X2]
D2#2  Diode  [HDR1X2]
FB1#2  BLM31A501
FB2#2  BLM31A501
FB7#2  BLM31A501
IC5#3  DM74ALS04BSJ  [SO-G14/Y1.7]  (part D of 6)
IC6#2  MAX3222ECWN  [DIP-18]
IC7#2  MAX483CPA  [DIP-8]
J6#2  Header 10X2  [HDR2X10]
J7#2  JTAG/ISP  [HDR1X10]
JP1#2  Header 6X2H  [HDR2X6]
JP2#2  Header 3X2  [HDR2X3]
JP2X5-1E#2  Header 5X2  [HDR2X5]
JP4-5#2  Header 3  [HDR1X3]
JP4-6#2  Header 3  [HDR1X3]
JP4-7#2  Header 3  [HDR1X3]
JP4-8#2  Header 3  [HDR1X3]
JP4-9#2  Header 3  [HDR1X3]
JP_4-1#2  Header 3  [HDR1X3]
JP_4-2#2  Header 3  [HDR1X3]
JP_4-3#2  Header 3  [HDR1X3]
JP_4-4#2  Header 3  [HDR1X3]
JP_4-10#2  Header 3  [HDR1X3]
R1#2  value 1M  [AXIAL-0.3]
R2#2  value 10K  [AXIAL-0.3]
R3#2  value 1M  [AXIAL-0.3]
R4#2  value 4K7  [AXIAL-0.3]
R23#2  value 560  [AXIAL-0.3]
R24#2  value 120  [AXIAL-0.3]
R25#2  value 560  [AXIAL-0.3]
R26#2  value 100  [AXIAL-0.3]
R27#2  value 10K  [AXIAL-0.3]
R32#2  Res1  value 0  [AXIAL-0.3]
RESETKEY#2  (no value)  [HDR1X2]
RN2A#2  (no value)  [AXIAL-0.3]
RN2B#2  (no value)  [AXIAL-0.3]
RN2C#2  (no value)  [AXIAL-0.3]
RN2D#2  (no value)  [AXIAL-0.3]
RS232#2  Header 10  [DSUB1.385-2H9]
RS485#2  Header 4  [DSUB1.385-2H9]
Y1#2  14.7456  [BCY-W2/D3.1]
Y2#2  32K768  [BCY-W2/D3.1]

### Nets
AGND5: A1.63(AGND) C5#2.2 J6#2.4 J6#2.6 J6#2.8 J6#2.10 J6#2.12 J6#2.14 J6#2.16 J6#2.18 J6#2.20 R3#2.2
AVCC5: A1.64(AVCC) C5#2.1 FB2#2.2 J6#2.1 J6#2.3
DC: D2#2.2(K) JP2X5-1E#2.1  [also labelled JP2X5 2]
GND: A1.22(GND) A1.53(GND) C1#2.1 C2#2.1 C3#2.1 C4#2.1 C22#2.1 C24#2.2 C25#2.2 C26#2.2 C27#2.2 C31#2.1 C37#2.1 IC7#2.5(GND) JP2X5-1E#2.3 JP4-6#2.3 JP4-8#2.3 JP_4-2#2.1 JP_4-4#2.3 JP_4-10#2.1 JP_4-10#2.3 R3#2.1 R23#2.1 R26#2.2 R27#2.2 R32#2.1 RESETKEY#2.2 RS232#2.10  [also labelled SH]
VCC5: C32#2.1 C37#2.2 FB1#2.1 FB2#2.1 FB7#2.2 R25#2.2
VCC5P: A1.21(VCC) A1.52(VCC) C3#2.2 C4#2.2 D1#2.2(K) FB1#2.2 R2#2.2 R4#2.2
VCC5S: C23#2.2 C28#2.2 FB7#2.1
A8: A1.35(PC0)
A9: A1.36(PC1)
A10: A1.37(PC2)
A11: A1.38(PC3)
A12: A1.39(PC4)
A13: A1.40(PC5)
A14: A1.41(PC6)
A15: A1.42(PC7)
ALE: A1.43(PG2)
AREF: A1.62(AREF)
D0: A1.44(PA7)
D1: A1.45(PA6)
D2: A1.46(PA5)
D3: A1.47(PA4)
D4: A1.48(PA3)
D5: A1.49(PA2)
D6: A1.50(PA1)
D7: A1.51(PA0)
DE485: IC7#2.3(DE) JP2#2.2 JP2#2.4 R27#2.1
DIHO: IC6#2.11(T2IN) IC7#2.4(DI)
HI: IC6#2.10(R2OUT) JP1#2.7
JP2X5 1: D2#2.1(A) JP2X5-1E#2.2 RS485#2.4
PB0: A1.10(S~{S}/PB0)
PB1: A1.11(SCK/PB1)
PB2: A1.12(MOSI/PB2)
PB3: A1.13(MISO/PB4)
PB4: A1.14(OC0/PB4)
PB5: A1.15(OC1A/PB5)
PB6: A1.16(OC1B/PB6)
PB7: A1.17(OC2/OC1C/PB7)
PD0: A1.25(SCL/INT0/PD0)
PD1: A1.26(SDA/INT1/PD1)
PD2: A1.27(RXD1/INT2/PD2) JP1#2.9
PD3: A1.28(TXD1/INT3/PD3) JP1#2.3
PD4: A1.29(IC1/PD4) JP2#2.6
PD5: A1.30(XCK1/PD5) JP2#2.1
PD6: A1.31(T1/PD6)
PD7: A1.32(T2/PB7)
PE3: JP1#2.5
PF0: A1.61(PF0) J6#2.5
PF1: A1.60(PF1) J6#2.7
PF2: A1.59(PF2) J6#2.9
PF3: A1.58(PF3) J6#2.11
PF4: A1.57(PF4) J6#2.13
PF5: A1.56(PF5) J6#2.15
PF6: A1.55(PF6) J6#2.17
PF7: A1.54(PF7) J6#2.19
R~{D}: A1.34(PG1)
RE485: IC7#2.2(~{RE}) JP2#2.3 JP2#2.5
RESET: IC5#3.8(Y) IC6#2.1(~{EN}) IC6#2.18(~{SHDN})
RESE~{T}: A1.1(PE~{N}) A1.20(RESE~{T}) C22#2.2 D1#2.1(A) IC5#3.9(A) R2#2.1 R4#2.1 RESETKEY#2.1
RO: IC7#2.1(RO)
RXD: IC6#2.13(R1OUT) JP1#2.11
TDO: JP_4-3#2.1
TXD: IC6#2.12(T1IN) JP1#2.1
W~{R}: A1.33(PG0)
NetA1_18: A1.18(PG3) Y2#2.2(OSC2)
NetA1_19: A1.19(PG4) Y2#2.1(OSC1)
NetA1_23: A1.23(XTAL2) C2#2.2 R1#2.2 Y1#2.2(OSC2)
NetC1#2_2: C1#2.2 R1#2.1 Y1#2.1(OSC1)
NetC23#2_1: C23#2.1 IC6#2.17(VCC)
NetC24#2_1: C24#2.1 RN2C#2.2 RS232#2.7
NetC25#2_1: C25#2.1 RN2D#2.2
NetC26#2_1: C26#2.1 C27#2.1 RN2A#2.2 RN2B#2.2 RS232#2.3 RS232#2.8
NetC28#2_1: C28#2.1 IC6#2.3(V+)
NetC29#2_1: C29#2.1 IC6#2.2(C1+)
NetC29#2_2: C29#2.2 IC6#2.4(C1-)
NetC30#2_1: C30#2.1 IC6#2.5(C2+)
NetC30#2_2: C30#2.2 IC6#2.6(C2-)
NetC31#2_2: C31#2.2 IC6#2.7(V-)
NetC32#2_2: C32#2.2 IC7#2.8(VCC)
NetIC6#2_8: IC6#2.8(T2OUT) RN2A#2.1
NetIC6#2_9: IC6#2.9(R2IN) RN2C#2.1
NetIC6#2_14: IC6#2.14(R1IN) RN2B#2.1
NetIC6#2_15: IC6#2.15(T1OUT) RN2D#2.1
NetIC7#2_6: IC7#2.6(A) JP2X5-1E#2.8 R24#2.1 RS485#2.1
NetIC7#2_7: IC7#2.7(B) JP2X5-1E#2.6 JP2X5-1E#2.10 RS485#2.2
NetJ7#2_1: J7#2.1 JP4-9#2.2
NetJ7#2_2: J7#2.2 JP4-8#2.2
NetJ7#2_3: J7#2.3 JP4-7#2.2
NetJ7#2_4: J7#2.4 JP4-6#2.2
NetJ7#2_5: J7#2.5 JP4-5#2.2
NetJ7#2_6: J7#2.6 JP_4-4#2.2
NetJ7#2_7: J7#2.7 JP_4-3#2.2
NetJ7#2_8: J7#2.8 JP_4-2#2.2
NetJ7#2_9: J7#2.9 JP_4-1#2.2
NetJ7#2_10: J7#2.10 JP_4-10#2.2
NetJP2X5-1E#2_4: JP2X5-1E#2.4 R26#2.1 RS485#2.3
NetJP2X5-1E#2_5: JP2X5-1E#2.5 JP2X5-1E#2.7 JP2X5-1E#2.9 R23#2.2 R24#2.2 R25#2.1
NetR32#2_2: R32#2.2 RS232#2.5

Not connected (* = marked no-connect by the designer): A1 2(PDI/RXD0/PE0) 3(PD0/TXD0/PE1) 4(XCK0/AIN0/PE2) 5(OC3A/AIN1/PE4) 6(OC3B/INT4/PE4) 7(OC3C/INT5/PE5) 8(T3/INT6/PE6) 9(IC3/INT/PE7) 24(XTAL1); IC5#3 7(GND) 14(VCC); IC6#2 16(GND); J6#2 2; JP1#2 2 4 6 8 10 12; JP4-5#2 1 3; JP4-6#2 1; JP4-7#2 1 3; JP4-8#2 1; JP4-9#2 1 3; JP_4-1#2 1 3; JP_4-2#2 3; JP_4-3#2 3; JP_4-4#2 1; RS232#2 1 2 4 6 9

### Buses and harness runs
bus ADDRESS:A[0..15]
bus DATA:D[0..7]
bus PORTB:PB[0..7]
bus PORTD:PD[0..7]
bus PORTE:PE[0..7]

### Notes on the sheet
- (near C31#2) RS232 CONFIGURATION FOR
- DEFULT CONNECT :
- JP1: 1-2 11-12
- Labels drawn without touching a wire or pin: AREF, DIHO, GND, HI, PB1, PE0, PE1, PE2, PE7, PF4, PF5, RESE~{T}, RO, TDI, VCC5

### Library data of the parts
A1 = ATMEGA128
C1#2 C2#2 C3#2 C4#2 C5#2 C22#2 C23#2 C24#2 C25#2 C26#2 C27#2 C32#2 C37#2 = Cap: as C1#1 on sheet ALLETHERNUT
C28#2 C29#2 C30#2 = Cap Pol2: as C19#1 on sheet ALLETHERNUT
C31#2 = (no symbol name): as C31#1 on sheet ALLETHERNUT
D1#2 = Diode: as D1#1 on sheet ALLETHERNUT
D2#2 = Diode: as D2#1 on sheet ALLETHERNUT
IC5#3 = DM74ALS04BSJ: as IC5#2 on sheet ALLETHERNUT
IC6#2 = MAX3222ECWN: as IC6#1 on sheet ALLETHERNUT
IC7#2 = MAX483CPA: as IC7#1 on sheet ALLETHERNUT
J6#2 = Header 10X2: as J6#1 on sheet ALLETHERNUT
J7#2 RS232#2 = Header 10: as J7#1 on sheet ALLETHERNUT
JP1#2 = Header 6X2H: as JP1#1 on sheet ALLETHERNUT
JP2#2 = Header 3X2: as JP2#1 on sheet ALLETHERNUT
JP2X5-1E#2 = Header 5X2: as JP2X5-1E#1 on sheet ALLETHERNUT
JP4-5#2 JP4-6#2 JP4-7#2 JP4-8#2 JP4-9#2 JP_4-1#2 JP_4-2#2 JP_4-3#2 JP_4-4#2 JP_4-10#2 = Header 3: as JP4-5#1 on sheet ALLETHERNUT
R1#2 R2#2 R3#2 R4#2 R23#2 R24#2 R25#2 R26#2 R27#2 R32#2 = Res1: as R1#1 on sheet ALLETHERNUT
RESETKEY#2 = MHDR1X2: as RESETKEY#1 on sheet ALLETHERNUT
RN2A#2 RN2B#2 RN2D#2 = (no symbol name): as RN2A#1 on sheet ALLETHERNUT
RN2C#2 = Res1: as RN2C#1 on sheet ALLETHERNUT
RS485#2 = Header 4: as RS485#1 on sheet ALLETHERNUT
Y1#2 Y2#2 = XTAL: as Y1#1 on sheet ALLETHERNUT

## Sheet CPLD.SCHDOC
size B
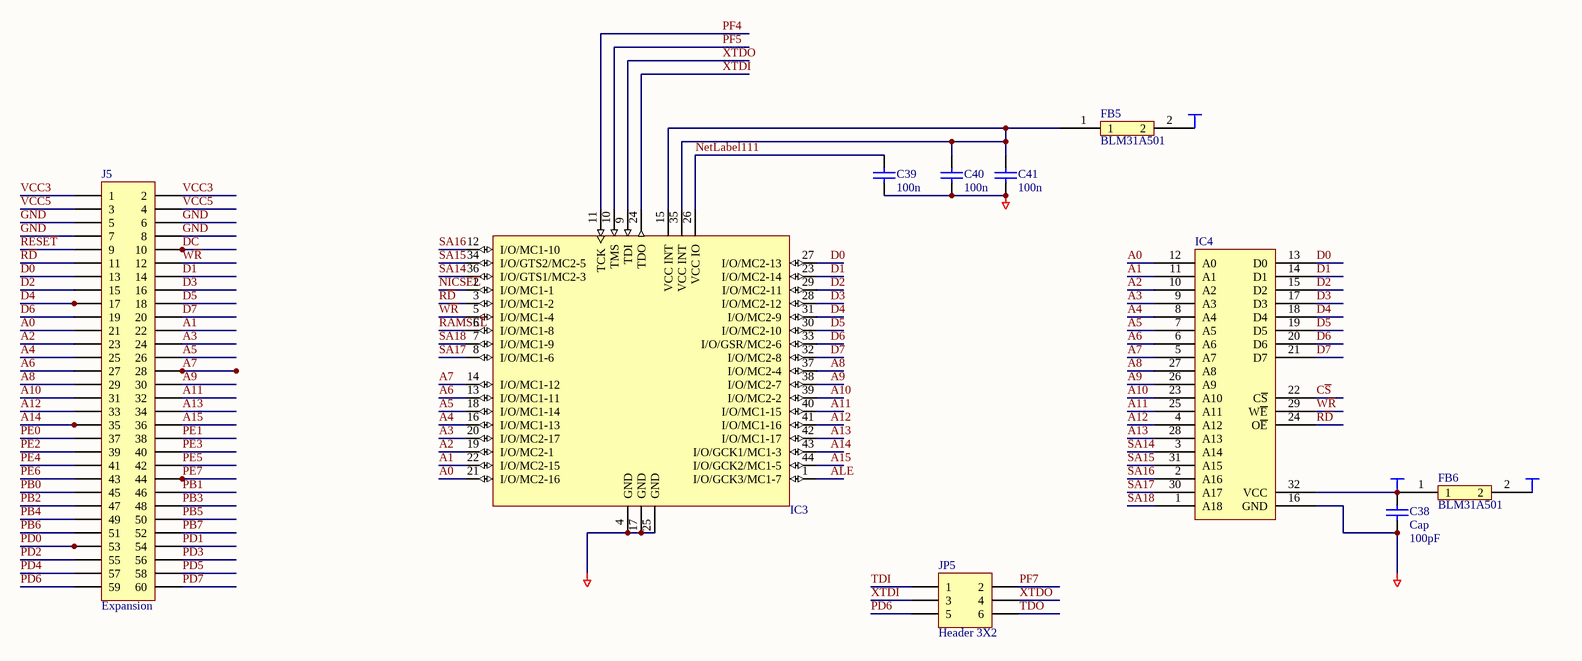
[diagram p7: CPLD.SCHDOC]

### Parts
(Parts that share a designator on the sheet are numbered #1, #2 ... from top to bottom, then left to right.)
C38#2  Cap  value 100pF  [RAD-0.1]
C39#2  value 100n  [RAD-0.1]
C40#2  value 100n  [RAD-0.1]
C41#2  value 100n  [RAD-0.1]
FB5#2  BLM31A501
FB6#2  BLM31A501
IC3#2  (no value)  [QFP10x10-G44/X.5N]
IC4#2  k6t4008  [SO-G32]
J5#2  Expansion  [HDR2X30]
JP5#2  Header 3X2  [HDR2X3]

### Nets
DC: J5#2.10
GND: C38#2.1 C39#2.1 C40#2.1 C41#2.1 IC3#2.4(GND) IC3#2.17(GND) IC3#2.25(GND) IC4#2.16(GND) J5#2.5 J5#2.6 J5#2.7 J5#2.8
VCC3: FB5#2.2 J5#2.1 J5#2.2
VCC5: FB6#2.2 J5#2.3 J5#2.4
VCC5R: C38#2.2 FB6#2.1 IC4#2.32(VCC)
A0: IC3#2.21(I/O/MC2-16) IC4#2.12(A0) J5#2.21
A1: IC3#2.22(I/O/MC2-15) IC4#2.11(A1) J5#2.22
A2: IC3#2.19(I/O/MC2-1) IC4#2.10(A2) J5#2.23
A3: IC3#2.20(I/O/MC2-17) IC4#2.9(A3) J5#2.24
A4: IC3#2.16(I/O/MC1-13) IC4#2.8(A4) J5#2.25
A5: IC3#2.18(I/O/MC1-14) IC4#2.7(A5) J5#2.26
A6: IC3#2.13(I/O/MC1-11) IC4#2.6(A6) J5#2.27
A7: IC3#2.14(I/O/MC1-12) IC4#2.5(A7) J5#2.28
A8: IC3#2.37(I/O/MC2-4) IC4#2.27(A8) J5#2.29
A9: IC3#2.38(I/O/MC2-7) IC4#2.26(A9) J5#2.30
A10: IC3#2.39(I/O/MC2-2) IC4#2.23(A10) J5#2.31
A11: IC3#2.40(I/O/MC1-15) IC4#2.25(A11) J5#2.32
A12: IC3#2.41(I/O/MC1-16) IC4#2.4(A12) J5#2.33
A13: IC3#2.42(I/O/MC1-17) IC4#2.28(A13) J5#2.34
A14: IC3#2.43(I/O/GCK1/MC1-3) J5#2.35
A15: IC3#2.44(I/O/GCK2/MC1-5) J5#2.36
ALE: IC3#2.1(I/O/GCK3/MC1-7)
C~{S}: IC4#2.22(C~{S})
D0: IC3#2.27(I/O/MC2-13) IC4#2.13(D0) J5#2.13
D1: IC3#2.23(I/O/MC2-14) IC4#2.14(D1) J5#2.14
D2: IC3#2.29(I/O/MC2-11) IC4#2.15(D2) J5#2.15
D3: IC3#2.28(I/O/MC2-12) IC4#2.17(D3) J5#2.16
D4: IC3#2.31(I/O/MC2-9) IC4#2.18(D4) J5#2.17
D5: IC3#2.30(I/O/MC2-10) IC4#2.19(D5) J5#2.18
D6: IC3#2.33(I/O/GSR/MC2-6) IC4#2.20(D6) J5#2.19
D7: IC3#2.32(I/O/MC2-8) IC4#2.21(D7) J5#2.20
NetLabel111: C39#2.2 IC3#2.26(VCC_IO)
NICSE~{L}: IC3#2.2(I/O/MC1-1)
PB0: J5#2.45
PB1: J5#2.46
PB2: J5#2.47
PB3: J5#2.48
PB4: J5#2.49
PB5: J5#2.50
PB6: J5#2.51
PB7: J5#2.52
PD0: J5#2.53
PD1: J5#2.54
PD2: J5#2.55
PD3: J5#2.56
PD4: J5#2.57
PD5: J5#2.58
PD6: J5#2.59 JP5#2.5
PD7: J5#2.60
PE0: J5#2.37
PE1: J5#2.38
PE2: J5#2.39
PE3: J5#2.40
PE4: J5#2.41
PE5: J5#2.42
PE6: J5#2.43
PE7: J5#2.44
PF4: IC3#2.11(TCK)
PF5: IC3#2.10(TMS)
PF7: JP5#2.2
RAMSE~{L}: IC3#2.6(I/O/MC1-8)
R~{D}: IC3#2.3(I/O/MC1-2) IC4#2.24(O~{E}) J5#2.11
RESE~{T}: J5#2.9
SA14: IC3#2.36(I/O/GTS1/MC2-3) IC4#2.3(A14)
SA15: IC3#2.34(I/O/GTS2/MC2-5) IC4#2.31(A15)
SA16: IC3#2.12(I/O/MC1-10) IC4#2.2(A16)
SA17: IC3#2.8(I/O/MC1-6) IC4#2.30(A17)
SA18: IC3#2.7(I/O/MC1-9) IC4#2.1(A18)
TDI: JP5#2.1
TDO: JP5#2.6
W~{R}: IC3#2.5(I/O/MC1-4) IC4#2.29(W~{E}) J5#2.12
XTDI: IC3#2.24(TDO) JP5#2.3
XTDO: IC3#2.9(TDI) JP5#2.4
NetC40#2_2: C40#2.2 C41#2.2 FB5#2.1 IC3#2.15(VCC_INT) IC3#2.35(VCC_INT)

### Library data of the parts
C38#2 C39#2 C40#2 C41#2 = Cap: as C1#1 on sheet ALLETHERNUT
IC3#2 = XC9536-10VQ44C: as IC3#1 on sheet ALLETHERNUT
J5#2 = Header 30X2: as J5#1 on sheet ALLETHERNUT
JP5#2 = Header 3X2: as JP2#1 on sheet ALLETHERNUT

## Sheet LAN91C111.SCHDOC
size B
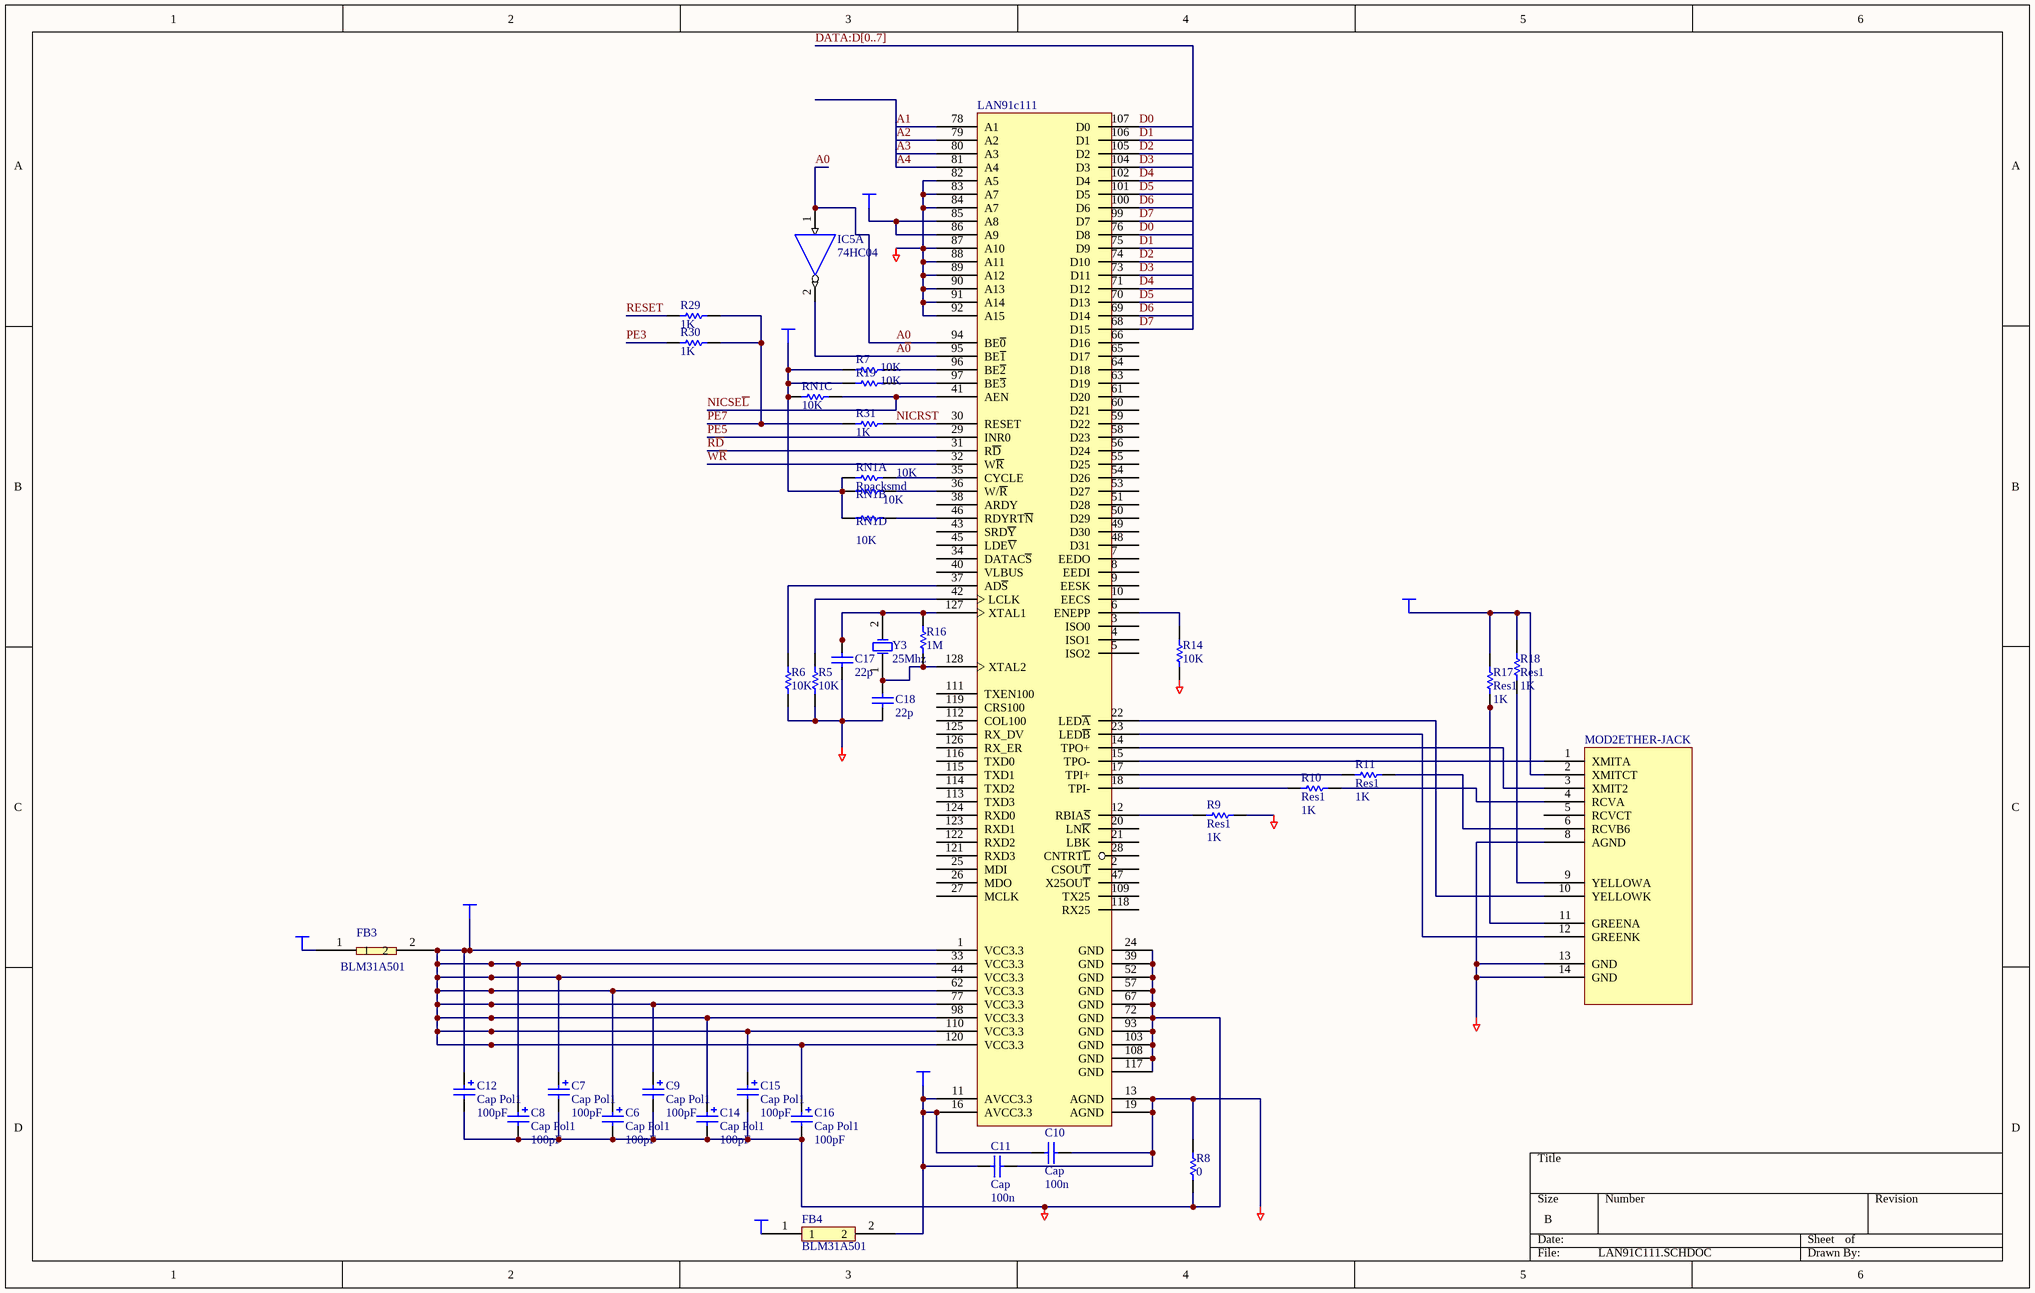
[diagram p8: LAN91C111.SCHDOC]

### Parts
(Parts that share a designator on the sheet are numbered #1, #2 ... from top to bottom, then left to right.)
C6#2  Cap Pol1  value 100pF  [RAD-0.1]
C7#2  Cap Pol1  value 100pF  [RAD-0.1]
C8#2  Cap Pol1  value 100pF  [RAD-0.1]
C9#2  Cap Pol1  value 100pF  [RAD-0.1]
C10#2  Cap  value 100n  [RAD-0.3]
C11#2  Cap  value 100n  [RAD-0.3]
C12#2  Cap Pol1  value 100pF  [RAD-0.1]
C14#2  Cap Pol1  value 100pF  [RAD-0.1]
C15#2  Cap Pol1  value 100pF  [RAD-0.1]
C16#2  Cap Pol1  value 100pF  [RAD-0.1]
C17#2  value 22p  [RAD-0.1]
C18#2  value 22p  [RAD-0.1]
FB3#2  BLM31A501
FB4#2  BLM31A501
IC5#4  74HC04  [DIP-14/D19.7]  (part A of 6)
LAN91c111  (no value)  [Model Name]
MOD2ETHER-JACK#2  (no value)
R5#2  value 10K  [AXIAL-0.3]
R6#2  value 10K  [AXIAL-0.3]
R7#2  value 10K  [AXIAL-0.3]
R8#2  value 0  [AXIAL-0.3]
R9#2  Res1  value 1K  [AXIAL-0.3]
R10#2  Res1  value 1K  [AXIAL-0.3]
R11#2  Res1  value 1K  [AXIAL-0.3]
R14#2  value 10K  [AXIAL-0.3]
R16#2  value 1M  [AXIAL-0.3]
R17#2  Res1  value 1K  [AXIAL-0.3]
R18#2  Res1  value 1K  [AXIAL-0.3]
R19#2  value 10K  [AXIAL-0.3]
R29#2  value 1K  [AXIAL-0.3]
R30#2  value 1K  [AXIAL-0.3]
R31#2  value 1K  [AXIAL-0.3]
RN1A#2  Rpacksmd  value 10K  [AXIAL-0.3]
RN1B#2  value 10K  [AXIAL-0.3]
RN1C#2  value 10K  [AXIAL-0.3]
RN1D#2  value 10K  [C3216-1206]
Y3#2  25Mhz  [RAD-0.3]

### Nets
AGND3: C10#2.2 C11#2.2 LAN91c111.13(AGND) LAN91c111.19(AGND) R8#2.2 R9#2.2
AVCC3: C10#2.1 C11#2.1 FB4#2.2 LAN91c111.11(AVCC3.3) LAN91c111.16(AVCC3.3) MOD2ETHER-JACK#2.2(XMITCT) R17#2.2 R18#2.2
GND: C6#2.2 C7#2.2 C8#2.2 C9#2.2 C12#2.2 C14#2.2 C15#2.2 C16#2.2 C17#2.1 C18#2.1 LAN91c111.24(GND) LAN91c111.39(GND) LAN91c111.52(GND) LAN91c111.57(GND) LAN91c111.67(GND) LAN91c111.72(GND) LAN91c111.82(A5) LAN91c111.83(A7) LAN91c111.84(A7) LAN91c111.87(A10) LAN91c111.88(A11) LAN91c111.89(A12) LAN91c111.90(A13) LAN91c111.91(A14) LAN91c111.92(A15) LAN91c111.93(GND) LAN91c111.103(GND) LAN91c111.108(GND) LAN91c111.117(GND) MOD2ETHER-JACK#2.8(AGND) MOD2ETHER-JACK#2.13(GND) MOD2ETHER-JACK#2.14(GND) R5#2.1 R6#2.1 R8#2.1 R14#2.1
VCC3: FB3#2.1 FB4#2.1
VCC3N: C6#2.1 C7#2.1 C8#2.1 C9#2.1 C12#2.1 C14#2.1 C15#2.1 C16#2.1 FB3#2.2 LAN91c111.1(VCC3.3) LAN91c111.33(VCC3.3) LAN91c111.44(VCC3.3) LAN91c111.62(VCC3.3) LAN91c111.77(VCC3.3) LAN91c111.85(A8) LAN91c111.86(A9) LAN91c111.98(VCC3.3) LAN91c111.110(VCC3.3) LAN91c111.120(VCC3.3) R7#2.1 R19#2.1 RN1A#2.1 RN1B#2.1 RN1C#2.1 RN1D#2.1
A0: IC5#4.1(A) LAN91c111.94(BE~{0})
A~{0}: IC5#4.2(Y) LAN91c111.95(BE~{1})
A1: LAN91c111.78(A1)
A2: LAN91c111.79(A2)
A3: LAN91c111.80(A3)
A4: LAN91c111.81(A4)
D0: LAN91c111.76(D8) LAN91c111.107(D0)
D1: LAN91c111.75(D9) LAN91c111.106(D1)
D2: LAN91c111.74(D10) LAN91c111.105(D2)
D3: LAN91c111.73(D11) LAN91c111.104(D3)
D4: LAN91c111.71(D12) LAN91c111.102(D4)
D5: LAN91c111.70(D13) LAN91c111.101(D5)
D6: LAN91c111.69(D14) LAN91c111.100(D6)
D7: LAN91c111.68(D15) LAN91c111.99(D7)
NICRST: LAN91c111.30(RESET) R31#2.2
NICSE~{L}: LAN91c111.41(AEN) RN1C#2.2
PE3: R30#2.1
PE5: LAN91c111.29(INR0)
PE7: R29#2.2 R30#2.2 R31#2.1
R~{D}: LAN91c111.31(R~{D})
RESET: R29#2.1
W~{R}: LAN91c111.32(W~{R})
NetC17#2_2: C17#2.2 LAN91c111.127(XTAL1) R16#2.2 Y3#2.2(OSC2)
NetC18#2_2: C18#2.2 LAN91c111.128(XTAL2) R16#2.1 Y3#2.1(OSC1)
NetLAN91c111_6: LAN91c111.6(ENEPP) R14#2.2
NetLAN91c111_12: LAN91c111.12(RBIA~{S}) R9#2.1
NetLAN91c111_14: LAN91c111.14(TPO+) MOD2ETHER-JACK#2.3(XMIT2)
NetLAN91c111_15: LAN91c111.15(TPO-) MOD2ETHER-JACK#2.1(XMITA)
NetLAN91c111_17: LAN91c111.17(TPI+) R11#2.1
NetLAN91c111_18: LAN91c111.18(TPI-) R10#2.1
NetLAN91c111_22: LAN91c111.22(LED~{A}) MOD2ETHER-JACK#2.10(YELLOWK)
NetLAN91c111_23: LAN91c111.23(LED~{B}) MOD2ETHER-JACK#2.12(GREENK)
NetLAN91c111_35: LAN91c111.35(CYCLE) RN1A#2.2
NetLAN91c111_36: LAN91c111.36(W/~{R}) RN1B#2.2
NetLAN91c111_37: LAN91c111.37(AD~{S}) R6#2.2
NetLAN91c111_42: LAN91c111.42(LCLK) R5#2.2
NetLAN91c111_46: LAN91c111.46(RDYRT~{N}) RN1D#2.2
NetLAN91c111_96: LAN91c111.96(BE~{2}) R7#2.2
NetLAN91c111_97: LAN91c111.97(BE~{3}) R19#2.2
NetMOD2ETHER-JACK#2_4: MOD2ETHER-JACK#2.4(RCVA) R10#2.2
NetMOD2ETHER-JACK#2_6: MOD2ETHER-JACK#2.6(RCVB6) R11#2.2
NetMOD2ETHER-JACK#2_9: MOD2ETHER-JACK#2.9(YELLOWA) R18#2.1
NetMOD2ETHER-JACK#2_11: MOD2ETHER-JACK#2.11(GREENA) R17#2.1

Not connected (* = marked no-connect by the designer): IC5#4 7(GND) 14(VCC); LAN91c111 2(CSOU~{T}) 3(ISO0) 4(ISO1) 5(ISO2) 7(EEDO) 8(EEDI) 9(EESK) 10(EECS) 20(LN~{K}) 21(LBK) 25(MDI) 26(MDO) 27(MCLK) 28(CNTRT~{L}) 34(DATAC~{S}) 38(ARDY) 40(VLBUS) 43(SRD~{Y}) 45(LDE~{V}) 47(X25OU~{T}) 48(D31) 49(D30) 50(D29) 51(D28) 53(D27) 54(D26) 55(D25) 56(D24) 58(D23) 59(D22) 60(D21) 61(D20) 63(D19) 64(D18) 65(D17) 66(D16) 109(TX25) 111(TXEN100) 112(COL100) 113(TXD3) 114(TXD2) 115(TXD1) 116(TXD0) 118(RX25) 119(CRS100) 121(RXD3) 122(RXD2) 123(RXD1) 124(RXD0) 125(RX_DV) 126(RX_ER); MOD2ETHER-JACK#2 5(RCVCT)

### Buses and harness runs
bus DATA:D[0..7]

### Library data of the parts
C6#2 C7#2 C8#2 C9#2 C12#2 C14#2 C15#2 C16#2 = Cap Pol1: as C6#1 on sheet ALLETHERNUT
C10#2 C11#2 C17#2 C18#2 = Cap: as C1#1 on sheet ALLETHERNUT
IC5#4 = (no symbol name): as IC5#1 on sheet ALLETHERNUT
LAN91c111 = SMSC: pin to pad: 2>132 3>27 4>21 5>44 6>17 7>51 8>50 9>49 10>48 11>76 12>15 13>130 14>26 15>23 16>110 17>25 18>14 19>131 20>93 21>100 23>39 24>120 25>12 26>13 27>99 28>16 39>11 44>5 48>10 49>53 50>54 51>55 53>56 54>9 55>58 56>59 58>60 59>61 60>62 61>63 63>64 64>65 65>66 66>8 76>2 93>3 99>101 100>102 101>20 102>104 104>105 105>106 106>107 107>24 112>78 113>7 114>6 116>4 117>129 118>98 119>77
MOD2ETHER-JACK#2 = ETHER
R5#2 R6#2 R8#2 R9#2 R10#2 R11#2 R14#2 R16#2 R17#2 R18#2 R29#2 R30#2 R31#2 RN1A#2 RN1B#2 RN1C#2 RN1D#2 = Res1: as R1#1 on sheet ALLETHERNUT
R7#2 R19#2 = (no symbol name): as R7#1 on sheet ALLETHERNUT
Y3#2 = XTAL: as Y1#1 on sheet ALLETHERNUT

## Sheet power.SCHDOC
size B
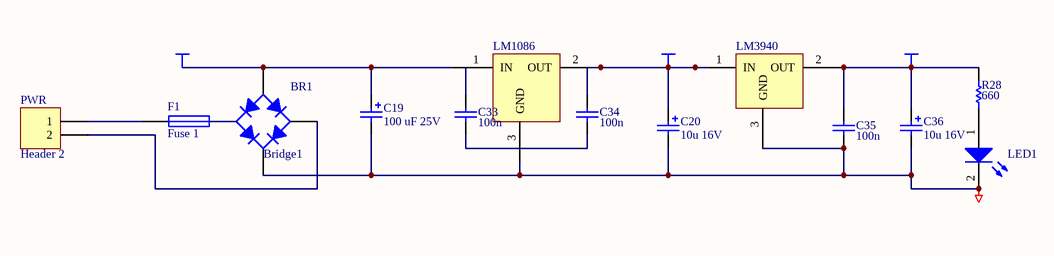
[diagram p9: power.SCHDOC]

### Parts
(Parts that share a designator on the sheet are numbered #1, #2 ... from top to bottom, then left to right.)
?#2  LM3940
BR1#2  Bridge1  [E-BIP-P4/D10]
C19#2  value 100 uF 25V  [RAD-0.1]
C20#2  value 10u 16V  [RAD-0.1]
C33#2  value 100n  [RAD-0.1]
C34#2  value 100n  [RAD-0.1]
C35#2  value 100n  [RAD-0.1]
C36#2  value 10u 16V  [RAD-0.1]
F1#2  Fuse 1  [PIN-W2/E2.8]
LED1#2  (no value)  [HDR1X2]
LM1086#2  (no value)  [Model Name]
PWR#2  Header 2  [HDR1X2]
R28#2  value 660  [AXIAL-0.3]

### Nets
DC: BR1#2.1(A) C19#2.1 LM1086#2.1(IN)
GND: ?#2.3(GND) BR1#2.3(K) C19#2.2 C20#2.2 C35#2.1 C36#2.2 LED1#2.2(K) LM1086#2.3(GND)
VCC3: ?#2.2(OUT) C35#2.2 C36#2.1 R28#2.2
VCC5: ?#2.1(IN) C20#2.1 C34#2.2 LM1086#2.2(OUT)
NetBR1#2_2: BR1#2.2(C) PWR#2.2
NetBR1#2_4: BR1#2.4(C) F1#2.2
NetC33#2_1: C33#2.1 C34#2.1
NetF1#2_1: F1#2.1 PWR#2.1
NetLED1#2_1: LED1#2.1(A) R28#2.1

Not connected (* = marked no-connect by the designer): C33#2 2

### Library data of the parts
BR1#2 = Bridge1: as BR1#1 on sheet ALLETHERNUT
C19#2 C20#2 C36#2 = Cap Pol2: as C19#1 on sheet ALLETHERNUT
C33#2 C34#2 C35#2 = Cap Semi: as C33#1 on sheet ALLETHERNUT
F1#2 = Fuse 1: as F1#1 on sheet ALLETHERNUT
LED1#2 = LED1: as LED1#1 on sheet ALLETHERNUT
LM1086#2 = LM1086
PWR#2 = Header 2: as PWR#1 on sheet ALLETHERNUT
R28#2 = Res1: as R1#1 on sheet ALLETHERNUT

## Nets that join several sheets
AGND3: ALLETHERNUT (7 pins), LAN91C111 (6 pins)
AGND5: ALLETHERNUT (12 pins), ATMEGA128 (12 pins)
AVCC3: ALLETHERNUT (8 pins), LAN91C111 (8 pins)
AVCC5: ALLETHERNUT (5 pins), ATMEGA128 (5 pins)
DC: ALLETHERNUT (6 pins), ATMEGA128 (D2#2.2 JP2X5-1E#2.1), CPLD (J5#2.10), power (BR1#2.1 C19#2.1 LM1086#2.1)
GND: ALLETHERNUT (83 pins), ATMEGA128 (28 pins), CPLD (12 pins), LAN91C111 (36 pins), power (8 pins)
VCC3: ALLETHERNUT (9 pins), CPLD (FB5#2.2 J5#2.1 J5#2.2), LAN91C111 (FB3#2.1 FB4#2.1), power (?#2.2 C35#2.2 C36#2.1 R28#2.2)
VCC3N: ALLETHERNUT (25 pins), LAN91C111 (25 pins)
VCC5: ALLETHERNUT (13 pins), ATMEGA128 (6 pins), CPLD (FB6#2.2 J5#2.3 J5#2.4), power (?#2.1 C20#2.1 C34#2.2 LM1086#2.2)
VCC5P: ALLETHERNUT (8 pins), ATMEGA128 (8 pins)
VCC5R: ALLETHERNUT (C38#1.2 FB6#1.1 IC4#1.32), CPLD (C38#2.2 FB6#2.1 IC4#2.32)
VCC5S: ALLETHERNUT (C23#1.2 C28#1.2 FB7#1.1), ATMEGA128 (C23#2.2 C28#2.2 FB7#2.1)
A0: ALLETHERNUT (5 pins), CPLD (IC3#2.21 IC4#2.12 J5#2.21), LAN91C111 (IC5#4.1 LAN91c111.94)
A~{0}: ALLETHERNUT (IC2.95 IC5#1.2), LAN91C111 (IC5#4.2 LAN91c111.95)
A1: ALLETHERNUT (IC2.78 IC3#1.22 IC4#1.11 J5#1.22), CPLD (IC3#2.22 IC4#2.11 J5#2.22), LAN91C111 (LAN91c111.78)
A2: ALLETHERNUT (IC2.79 IC3#1.19 IC4#1.10 J5#1.23), CPLD (IC3#2.19 IC4#2.10 J5#2.23), LAN91C111 (LAN91c111.79)
A3: ALLETHERNUT (IC2.80 IC3#1.20 IC4#1.9 J5#1.24), CPLD (IC3#2.20 IC4#2.9 J5#2.24), LAN91C111 (LAN91c111.80)
A4: ALLETHERNUT (IC2.81 IC3#1.16 IC4#1.8 J5#1.25), CPLD (IC3#2.16 IC4#2.8 J5#2.25), LAN91C111 (LAN91c111.81)
A5: ALLETHERNUT (IC3#1.18 IC4#1.7 J5#1.26), CPLD (IC3#2.18 IC4#2.7 J5#2.26)
A6: ALLETHERNUT (IC3#1.13 IC4#1.6 J5#1.27), CPLD (IC3#2.13 IC4#2.6 J5#2.27)
A7: ALLETHERNUT (IC3#1.14 IC4#1.5 J5#1.28), CPLD (IC3#2.14 IC4#2.5 J5#2.28)
A8: ALLETHERNUT (IC1.35 IC3#1.37 IC4#1.27 J5#1.29), ATMEGA128 (A1.35), CPLD (IC3#2.37 IC4#2.27 J5#2.29)
A9: ALLETHERNUT (IC1.36 IC3#1.38 IC4#1.26 J5#1.30), ATMEGA128 (A1.36), CPLD (IC3#2.38 IC4#2.26 J5#2.30)
A10: ALLETHERNUT (IC1.37 IC3#1.39 IC4#1.23 J5#1.31), ATMEGA128 (A1.37), CPLD (IC3#2.39 IC4#2.23 J5#2.31)
A11: ALLETHERNUT (IC1.38 IC3#1.40 IC4#1.25 J5#1.32), ATMEGA128 (A1.38), CPLD (IC3#2.40 IC4#2.25 J5#2.32)
A12: ALLETHERNUT (IC1.39 IC3#1.41 IC4#1.4 J5#1.33), ATMEGA128 (A1.39), CPLD (IC3#2.41 IC4#2.4 J5#2.33)
A13: ALLETHERNUT (IC1.40 IC3#1.42 IC4#1.28 J5#1.34), ATMEGA128 (A1.40), CPLD (IC3#2.42 IC4#2.28 J5#2.34)
A14: ALLETHERNUT (IC1.41 IC3#1.43 J5#1.35), ATMEGA128 (A1.41), CPLD (IC3#2.43 J5#2.35)
A15: ALLETHERNUT (IC1.42 IC3#1.44 J5#1.36), ATMEGA128 (A1.42), CPLD (IC3#2.44 J5#2.36)
ALE: ALLETHERNUT (IC1.43 IC3#1.1), ATMEGA128 (A1.43), CPLD (IC3#2.1)
AREF: ALLETHERNUT (IC1.62), ATMEGA128 (A1.62)
C~{S}: ALLETHERNUT (IC4#1.22), CPLD (IC4#2.22)
D0: ALLETHERNUT (6 pins), ATMEGA128 (A1.44), CPLD (IC3#2.27 IC4#2.13 J5#2.13), LAN91C111 (LAN91c111.76 LAN91c111.107)
D1: ALLETHERNUT (6 pins), ATMEGA128 (A1.45), CPLD (IC3#2.23 IC4#2.14 J5#2.14), LAN91C111 (LAN91c111.75 LAN91c111.106)
D2: ALLETHERNUT (6 pins), ATMEGA128 (A1.46), CPLD (IC3#2.29 IC4#2.15 J5#2.15), LAN91C111 (LAN91c111.74 LAN91c111.105)
D3: ALLETHERNUT (6 pins), ATMEGA128 (A1.47), CPLD (IC3#2.28 IC4#2.17 J5#2.16), LAN91C111 (LAN91c111.73 LAN91c111.104)
D4: ALLETHERNUT (6 pins), ATMEGA128 (A1.48), CPLD (IC3#2.31 IC4#2.18 J5#2.17), LAN91C111 (LAN91c111.71 LAN91c111.102)
D5: ALLETHERNUT (6 pins), ATMEGA128 (A1.49), CPLD (IC3#2.30 IC4#2.19 J5#2.18), LAN91C111 (LAN91c111.70 LAN91c111.101)
D6: ALLETHERNUT (6 pins), ATMEGA128 (A1.50), CPLD (IC3#2.33 IC4#2.20 J5#2.19), LAN91C111 (LAN91c111.69 LAN91c111.100)
D7: ALLETHERNUT (6 pins), ATMEGA128 (A1.51), CPLD (IC3#2.32 IC4#2.21 J5#2.20), LAN91C111 (LAN91c111.68 LAN91c111.99)
DE485: ALLETHERNUT (IC7#1.3 JP2#1.2 JP2#1.4 R27#1.1), ATMEGA128 (IC7#2.3 JP2#2.2 JP2#2.4 R27#2.1)
DIHO: ALLETHERNUT (IC6#1.11 IC7#1.4), ATMEGA128 (IC6#2.11 IC7#2.4)
HI: ALLETHERNUT (IC6#1.10 JP1#1.7), ATMEGA128 (IC6#2.10 JP1#2.7)
JP2X5 1: ALLETHERNUT (D2#1.1 JP2X5-1E#1.2 RS485#1.4), ATMEGA128 (D2#2.1 JP2X5-1E#2.2 RS485#2.4)
NetLabel111: ALLETHERNUT (C39#1.2 IC3#1.26), CPLD (C39#2.2 IC3#2.26)
NICRST: ALLETHERNUT (IC2.30 R31#1.2), LAN91C111 (LAN91c111.30 R31#2.2)
NICSE~{L}: ALLETHERNUT (IC2.41 IC3#1.2 RN1C#1.2), CPLD (IC3#2.2), LAN91C111 (LAN91c111.41 RN1C#2.2)
PB0: ALLETHERNUT (IC1.10 J5#1.45), ATMEGA128 (A1.10), CPLD (J5#2.45)
PB1: ALLETHERNUT (IC1.11 J5#1.46), ATMEGA128 (A1.11), CPLD (J5#2.46)
PB2: ALLETHERNUT (IC1.12 J5#1.47), ATMEGA128 (A1.12), CPLD (J5#2.47)
PB3: ALLETHERNUT (IC1.13 J5#1.48), ATMEGA128 (A1.13), CPLD (J5#2.48)
PB4: ALLETHERNUT (IC1.14 J5#1.49), ATMEGA128 (A1.14), CPLD (J5#2.49)
PB5: ALLETHERNUT (IC1.15 J5#1.50), ATMEGA128 (A1.15), CPLD (J5#2.50)
PB6: ALLETHERNUT (IC1.16 J5#1.51), ATMEGA128 (A1.16), CPLD (J5#2.51)
PB7: ALLETHERNUT (IC1.17 J5#1.52), ATMEGA128 (A1.17), CPLD (J5#2.52)
PD0: ALLETHERNUT (IC1.25 J5#1.53), ATMEGA128 (A1.25), CPLD (J5#2.53)
PD1: ALLETHERNUT (IC1.26 J5#1.54), ATMEGA128 (A1.26), CPLD (J5#2.54)
PD2: ALLETHERNUT (IC1.27 J5#1.55 JP1#1.9), ATMEGA128 (A1.27 JP1#2.9), CPLD (J5#2.55)
PD3: ALLETHERNUT (IC1.28 J5#1.56 JP1#1.3), ATMEGA128 (A1.28 JP1#2.3), CPLD (J5#2.56)
PD4: ALLETHERNUT (IC1.29 J5#1.57 JP2#1.6), ATMEGA128 (A1.29 JP2#2.6), CPLD (J5#2.57)
PD5: ALLETHERNUT (IC1.30 J5#1.58 JP2#1.1), ATMEGA128 (A1.30 JP2#2.1), CPLD (J5#2.58)
PD6: ALLETHERNUT (IC1.31 J5#1.59 JP5#1.5), ATMEGA128 (A1.31), CPLD (J5#2.59 JP5#2.5)
PD7: ALLETHERNUT (IC1.32 J5#1.60), ATMEGA128 (A1.32), CPLD (J5#2.60)
PE0: ALLETHERNUT (J5#1.37), CPLD (J5#2.37)
PE1: ALLETHERNUT (J5#1.38), CPLD (J5#2.38)
PE2: ALLETHERNUT (J5#1.39), CPLD (J5#2.39)
PE3: ALLETHERNUT (J5#1.40 JP1#1.5 R30#1.1), ATMEGA128 (JP1#2.5), CPLD (J5#2.40), LAN91C111 (R30#2.1)
PE4: ALLETHERNUT (J5#1.41), CPLD (J5#2.41)
PE5: ALLETHERNUT (IC2.29 J5#1.42), CPLD (J5#2.42), LAN91C111 (LAN91c111.29)
PE6: ALLETHERNUT (J5#1.43), CPLD (J5#2.43)
PE7: ALLETHERNUT (J5#1.44 R29#1.2 R30#1.2 R31#1.1), CPLD (J5#2.44), LAN91C111 (R29#2.2 R30#2.2 R31#2.1)
PF0: ALLETHERNUT (IC1.61 J6#1.5), ATMEGA128 (A1.61 J6#2.5)
PF1: ALLETHERNUT (IC1.60 J6#1.7), ATMEGA128 (A1.60 J6#2.7)
PF2: ALLETHERNUT (IC1.59 J6#1.9), ATMEGA128 (A1.59 J6#2.9)
PF3: ALLETHERNUT (IC1.58 J6#1.11), ATMEGA128 (A1.58 J6#2.11)
PF4: ALLETHERNUT (IC1.57 IC3#1.11 J6#1.13), ATMEGA128 (A1.57 J6#2.13), CPLD (IC3#2.11)
PF5: ALLETHERNUT (IC1.56 IC3#1.10 J6#1.15), ATMEGA128 (A1.56 J6#2.15), CPLD (IC3#2.10)
PF6: ALLETHERNUT (IC1.55 J6#1.17), ATMEGA128 (A1.55 J6#2.17)
PF7: ALLETHERNUT (IC1.54 J6#1.19 JP5#1.2), ATMEGA128 (A1.54 J6#2.19), CPLD (JP5#2.2)
RAMSE~{L}: ALLETHERNUT (IC3#1.6), CPLD (IC3#2.6)
R~{D}: ALLETHERNUT (5 pins), ATMEGA128 (A1.34), CPLD (IC3#2.3 IC4#2.24 J5#2.11), LAN91C111 (LAN91c111.31)
RE485: ALLETHERNUT (IC7#1.2 JP2#1.3 JP2#1.5), ATMEGA128 (IC7#2.2 JP2#2.3 JP2#2.5)
RESET: ALLETHERNUT (IC5#2.8 IC6#1.1 R29#1.1), ATMEGA128 (IC5#3.8 IC6#2.1 IC6#2.18), LAN91C111 (R29#2.1)
RESE~{T}: ALLETHERNUT (10 pins), ATMEGA128 (8 pins), CPLD (J5#2.9)
RO: ALLETHERNUT (IC7#1.1), ATMEGA128 (IC7#2.1)
RXD: ALLETHERNUT (IC6#1.13 JP1#1.11), ATMEGA128 (IC6#2.13 JP1#2.11)
SA14: ALLETHERNUT (IC3#1.36 IC4#1.3), CPLD (IC3#2.36 IC4#2.3)
SA15: ALLETHERNUT (IC3#1.34 IC4#1.31), CPLD (IC3#2.34 IC4#2.31)
SA16: ALLETHERNUT (IC3#1.12 IC4#1.2), CPLD (IC3#2.12 IC4#2.2)
SA17: ALLETHERNUT (IC3#1.8 IC4#1.30), CPLD (IC3#2.8 IC4#2.30)
SA18: ALLETHERNUT (IC3#1.7 IC4#1.1), CPLD (IC3#2.7 IC4#2.1)
TDI: ALLETHERNUT (JP5#1.1), CPLD (JP5#2.1)
TDO: ALLETHERNUT (JP5#1.6 JP_4-3#1.1), ATMEGA128 (JP_4-3#2.1), CPLD (JP5#2.6)
TXD: ALLETHERNUT (IC6#1.12 JP1#1.1), ATMEGA128 (IC6#2.12 JP1#2.1)
W~{R}: ALLETHERNUT (5 pins), ATMEGA128 (A1.33), CPLD (IC3#2.5 IC4#2.29 J5#2.12), LAN91C111 (LAN91c111.32)
XTDI: ALLETHERNUT (IC3#1.24 JP5#1.3), CPLD (IC3#2.24 JP5#2.3)
XTDO: ALLETHERNUT (IC3#1.9 JP5#1.4), CPLD (IC3#2.9 JP5#2.4)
